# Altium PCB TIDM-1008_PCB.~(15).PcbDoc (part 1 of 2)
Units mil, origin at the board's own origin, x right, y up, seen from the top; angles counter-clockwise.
Board outline 2200 x 2300 mil, 4 copper layers (Top Layer, Power Layer, Ground Plane, Bottom Layer), stack 79.834 mil thick; 196 components, 111 nets, 520 pads, 167 vias.
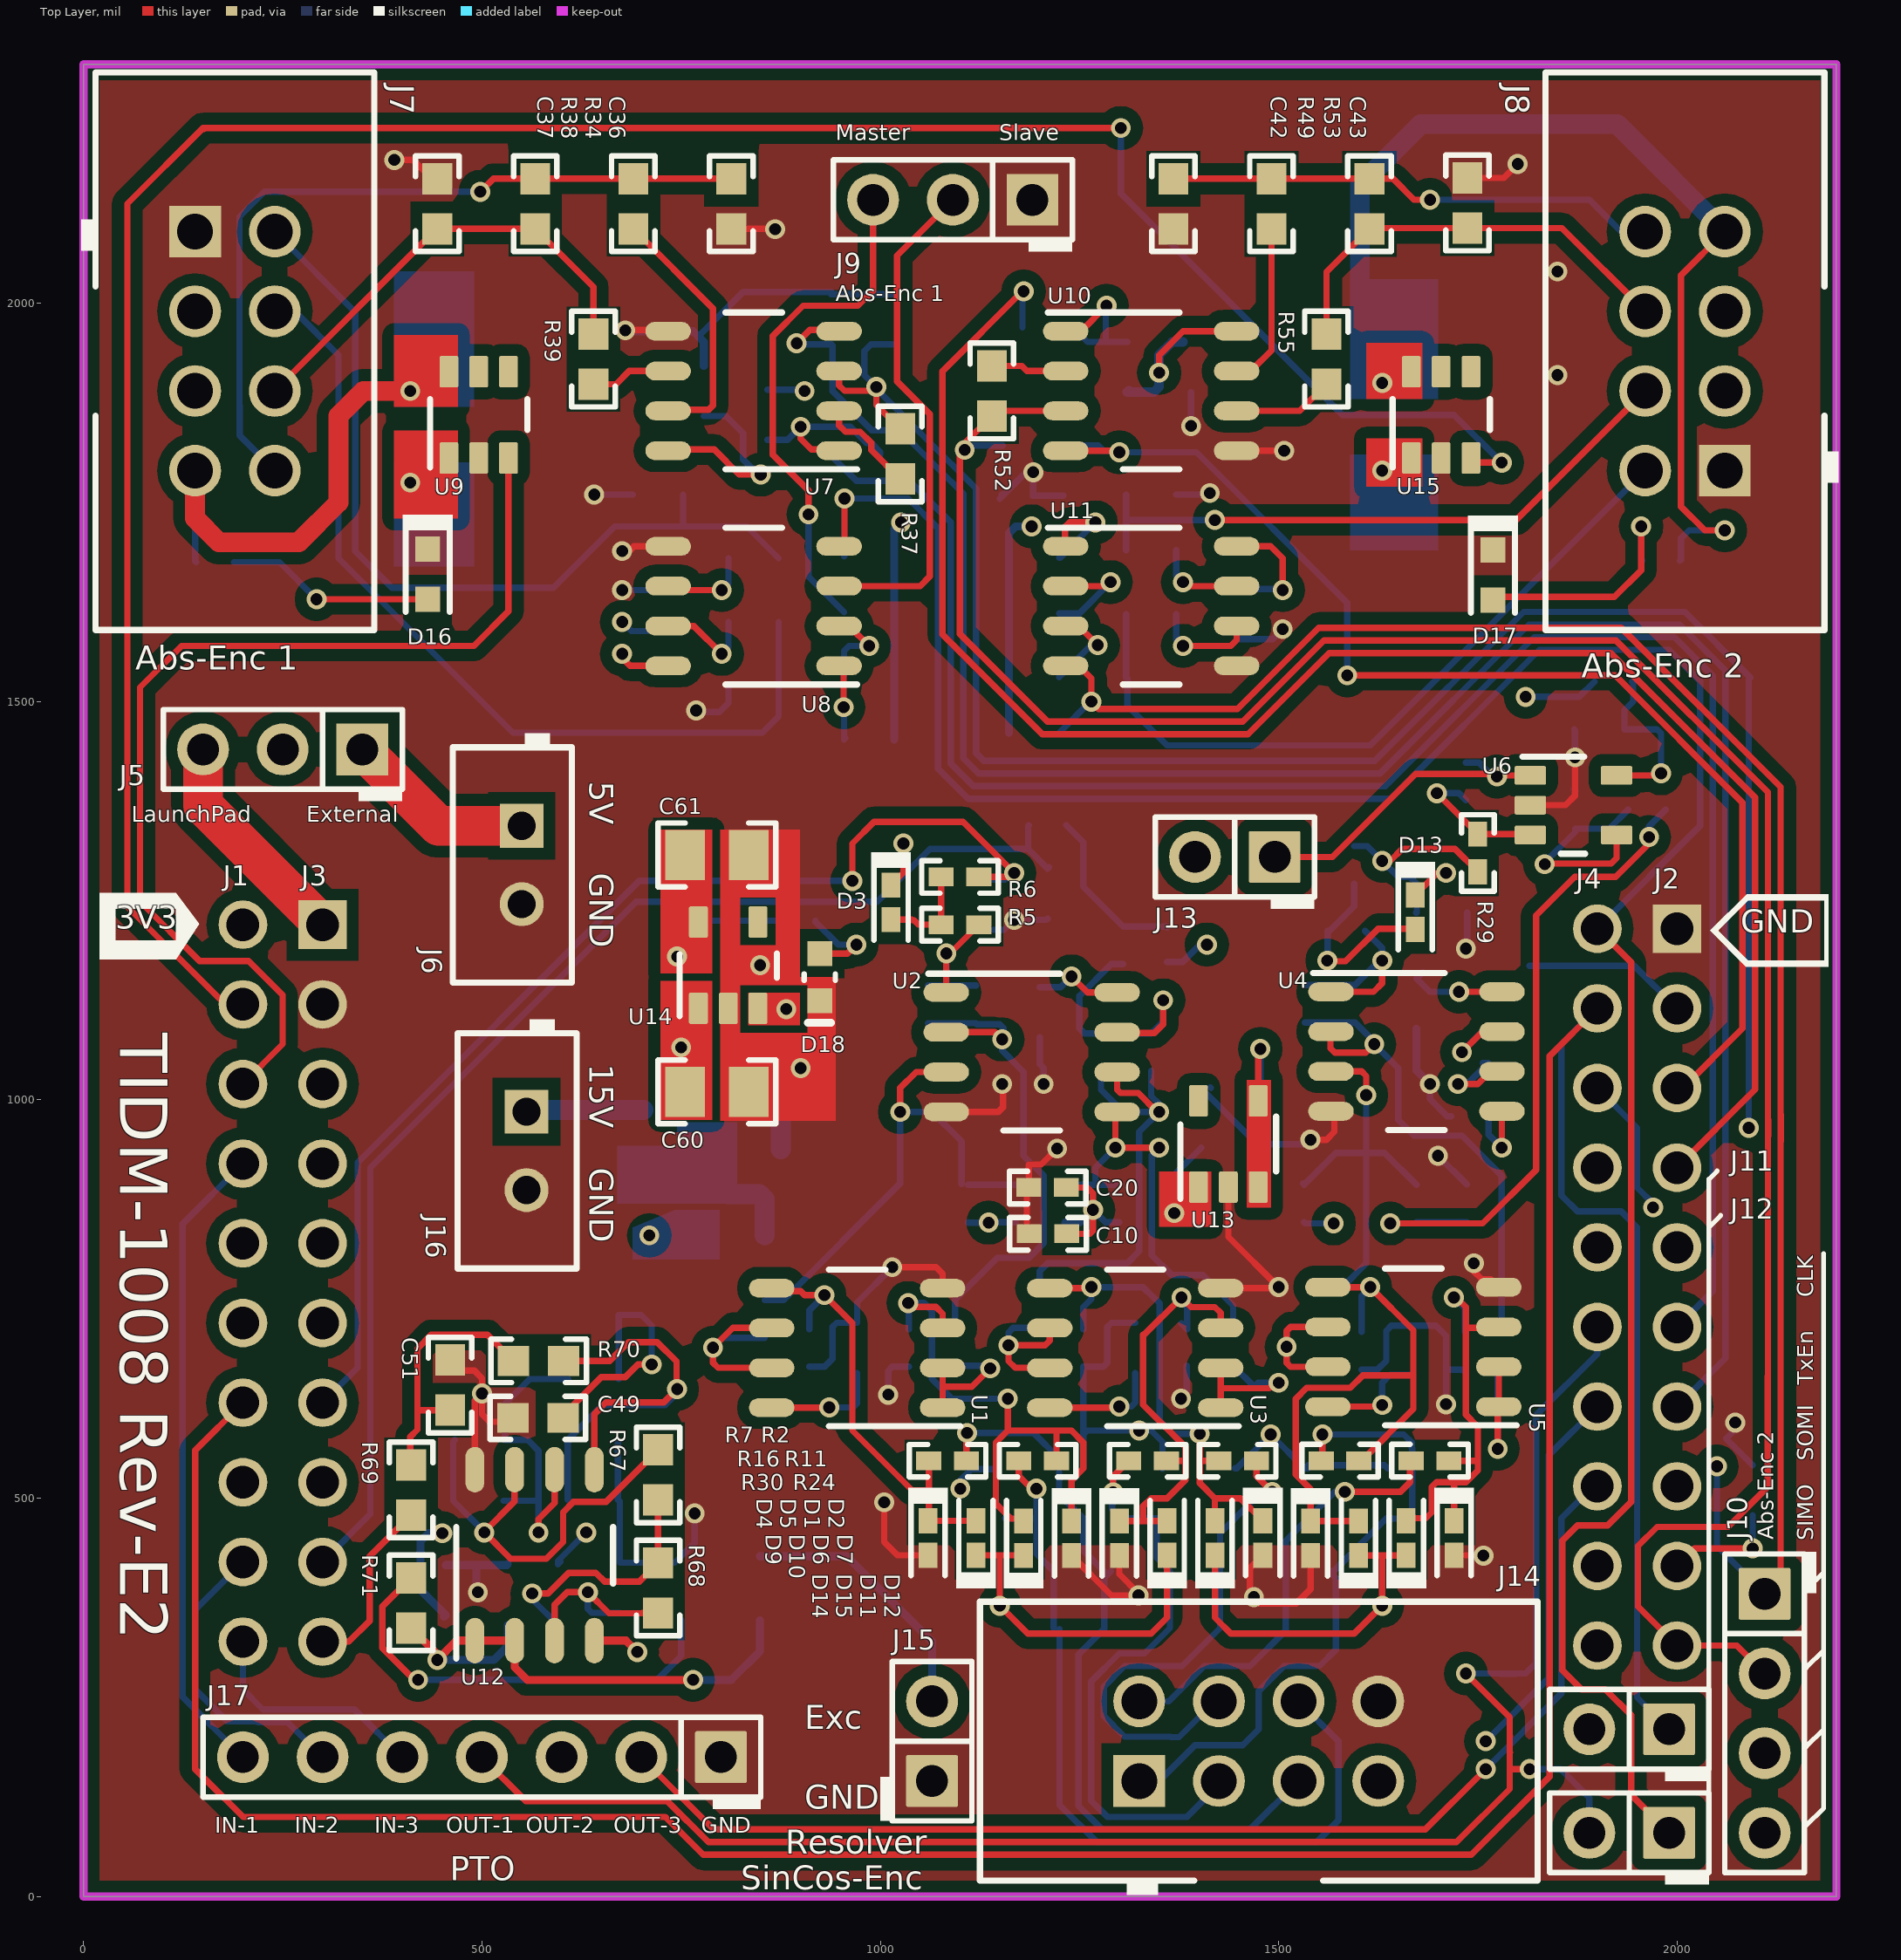
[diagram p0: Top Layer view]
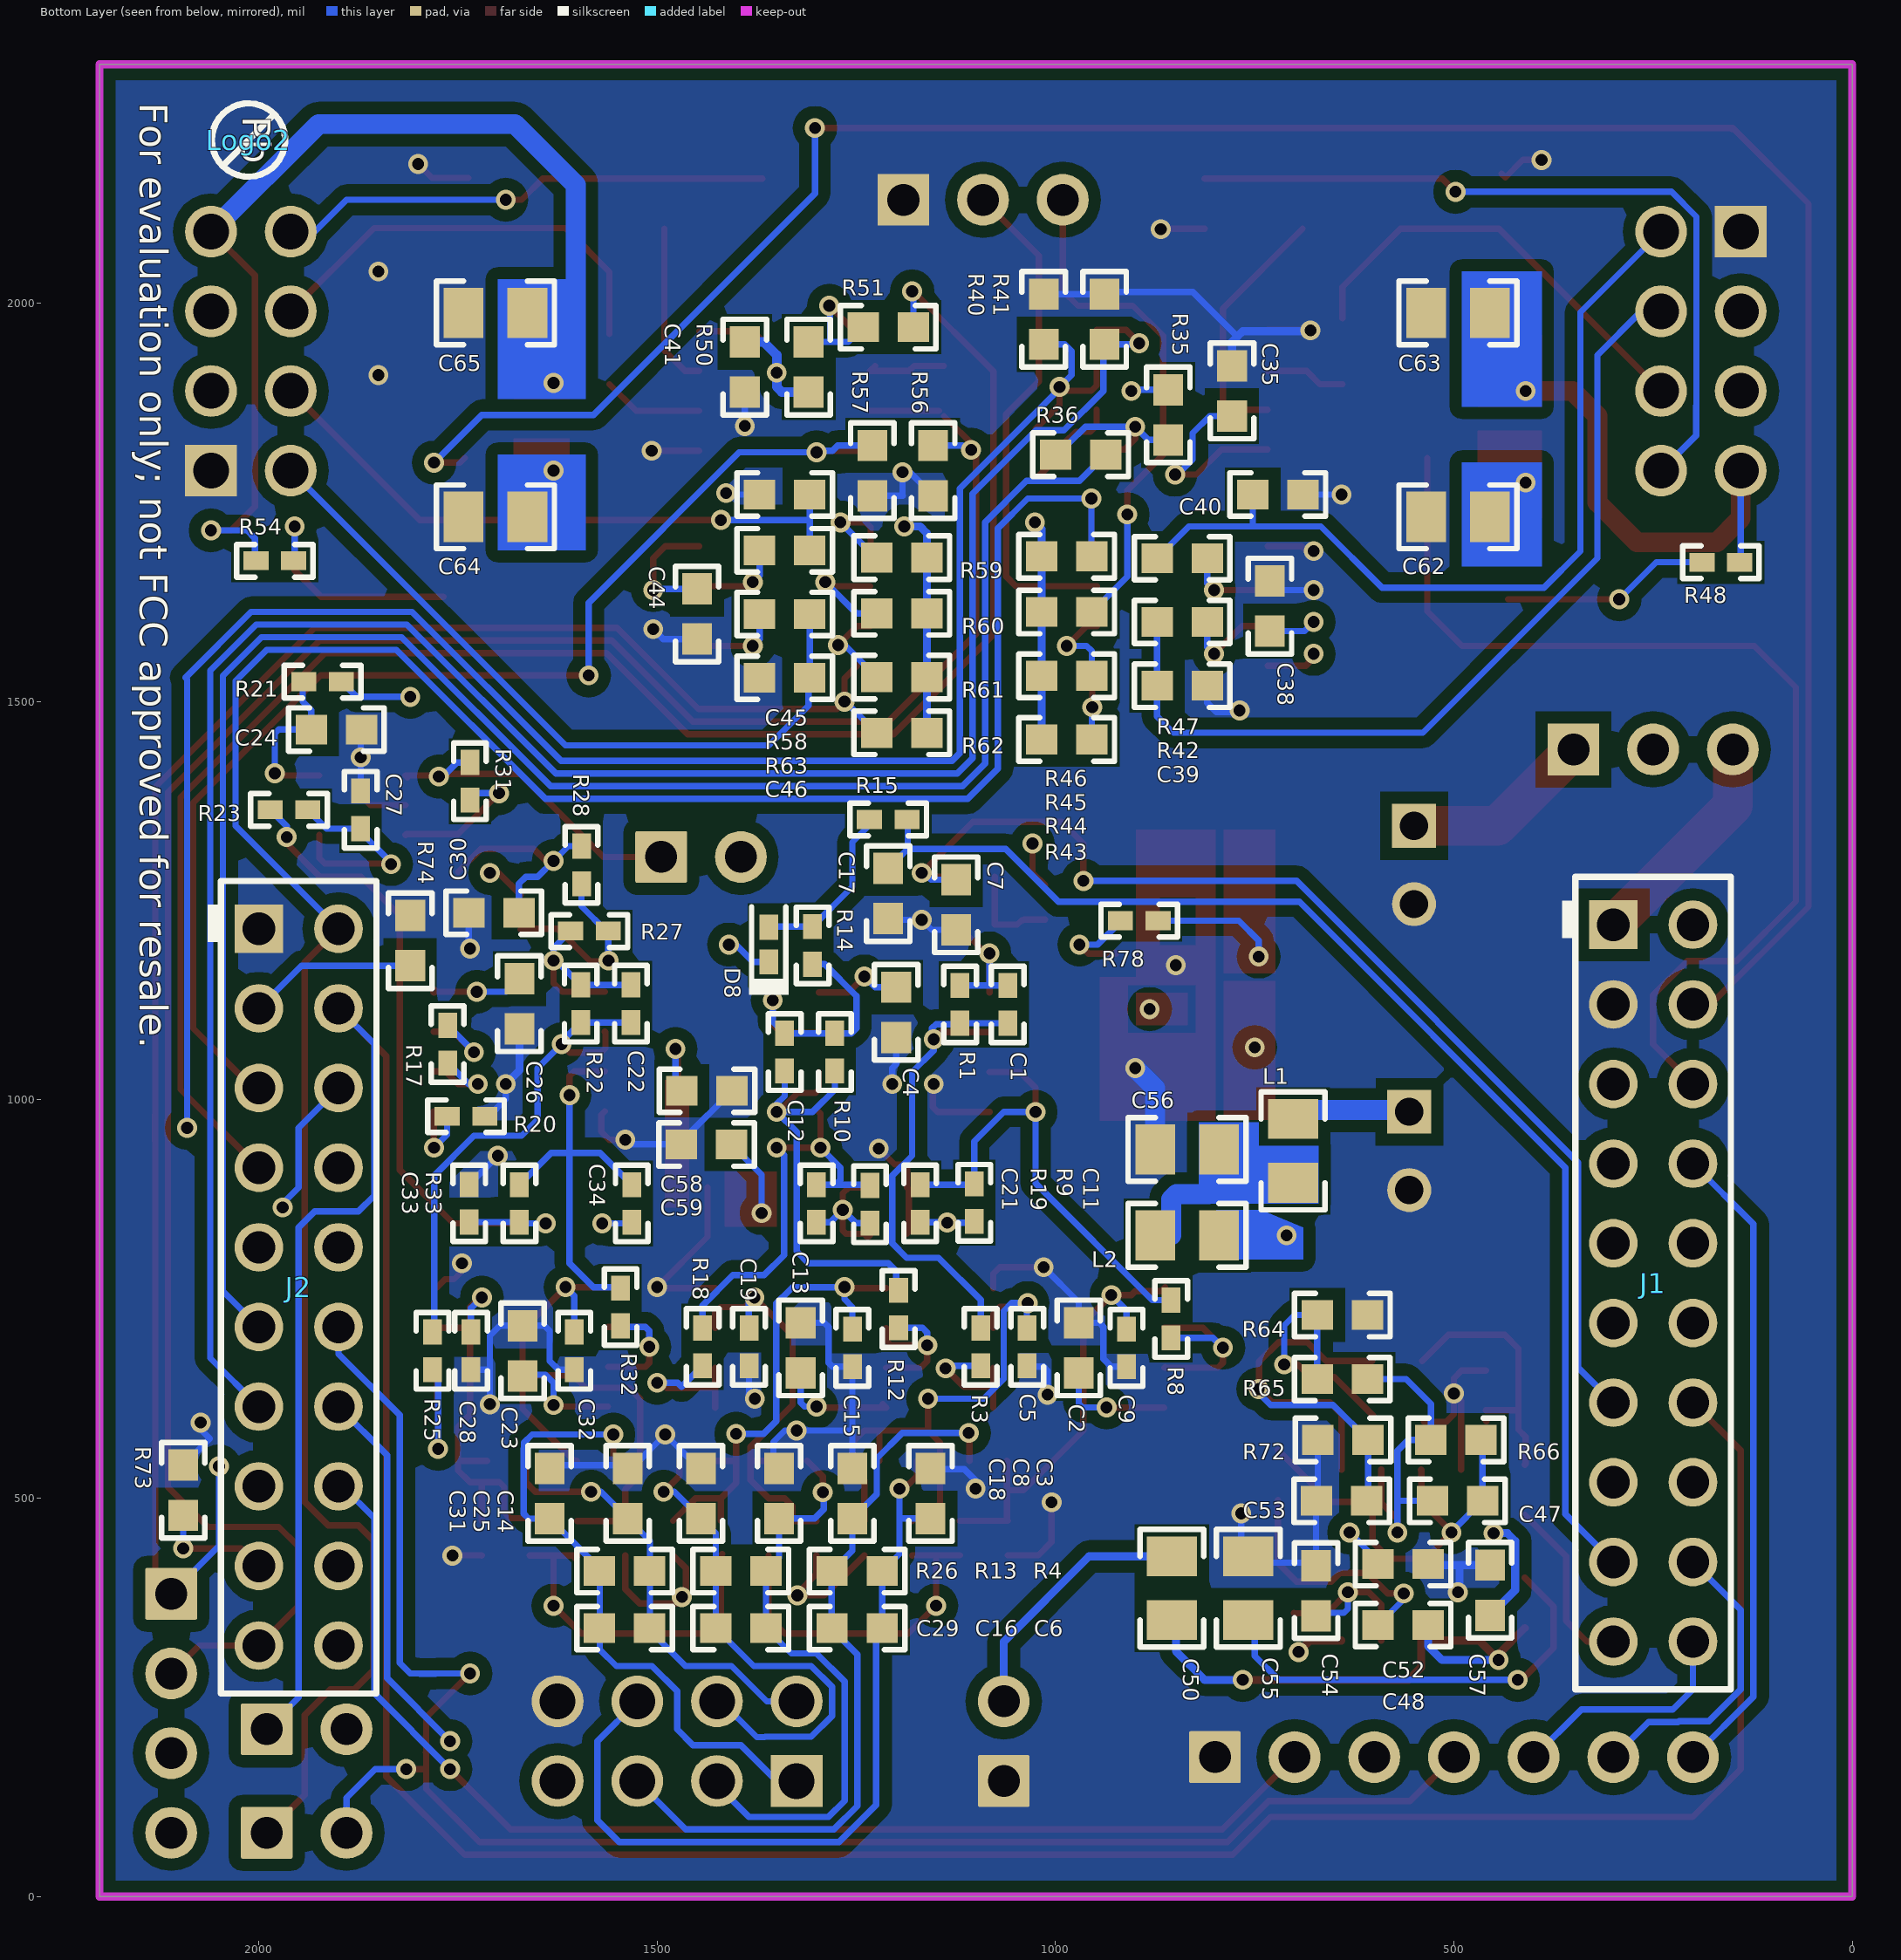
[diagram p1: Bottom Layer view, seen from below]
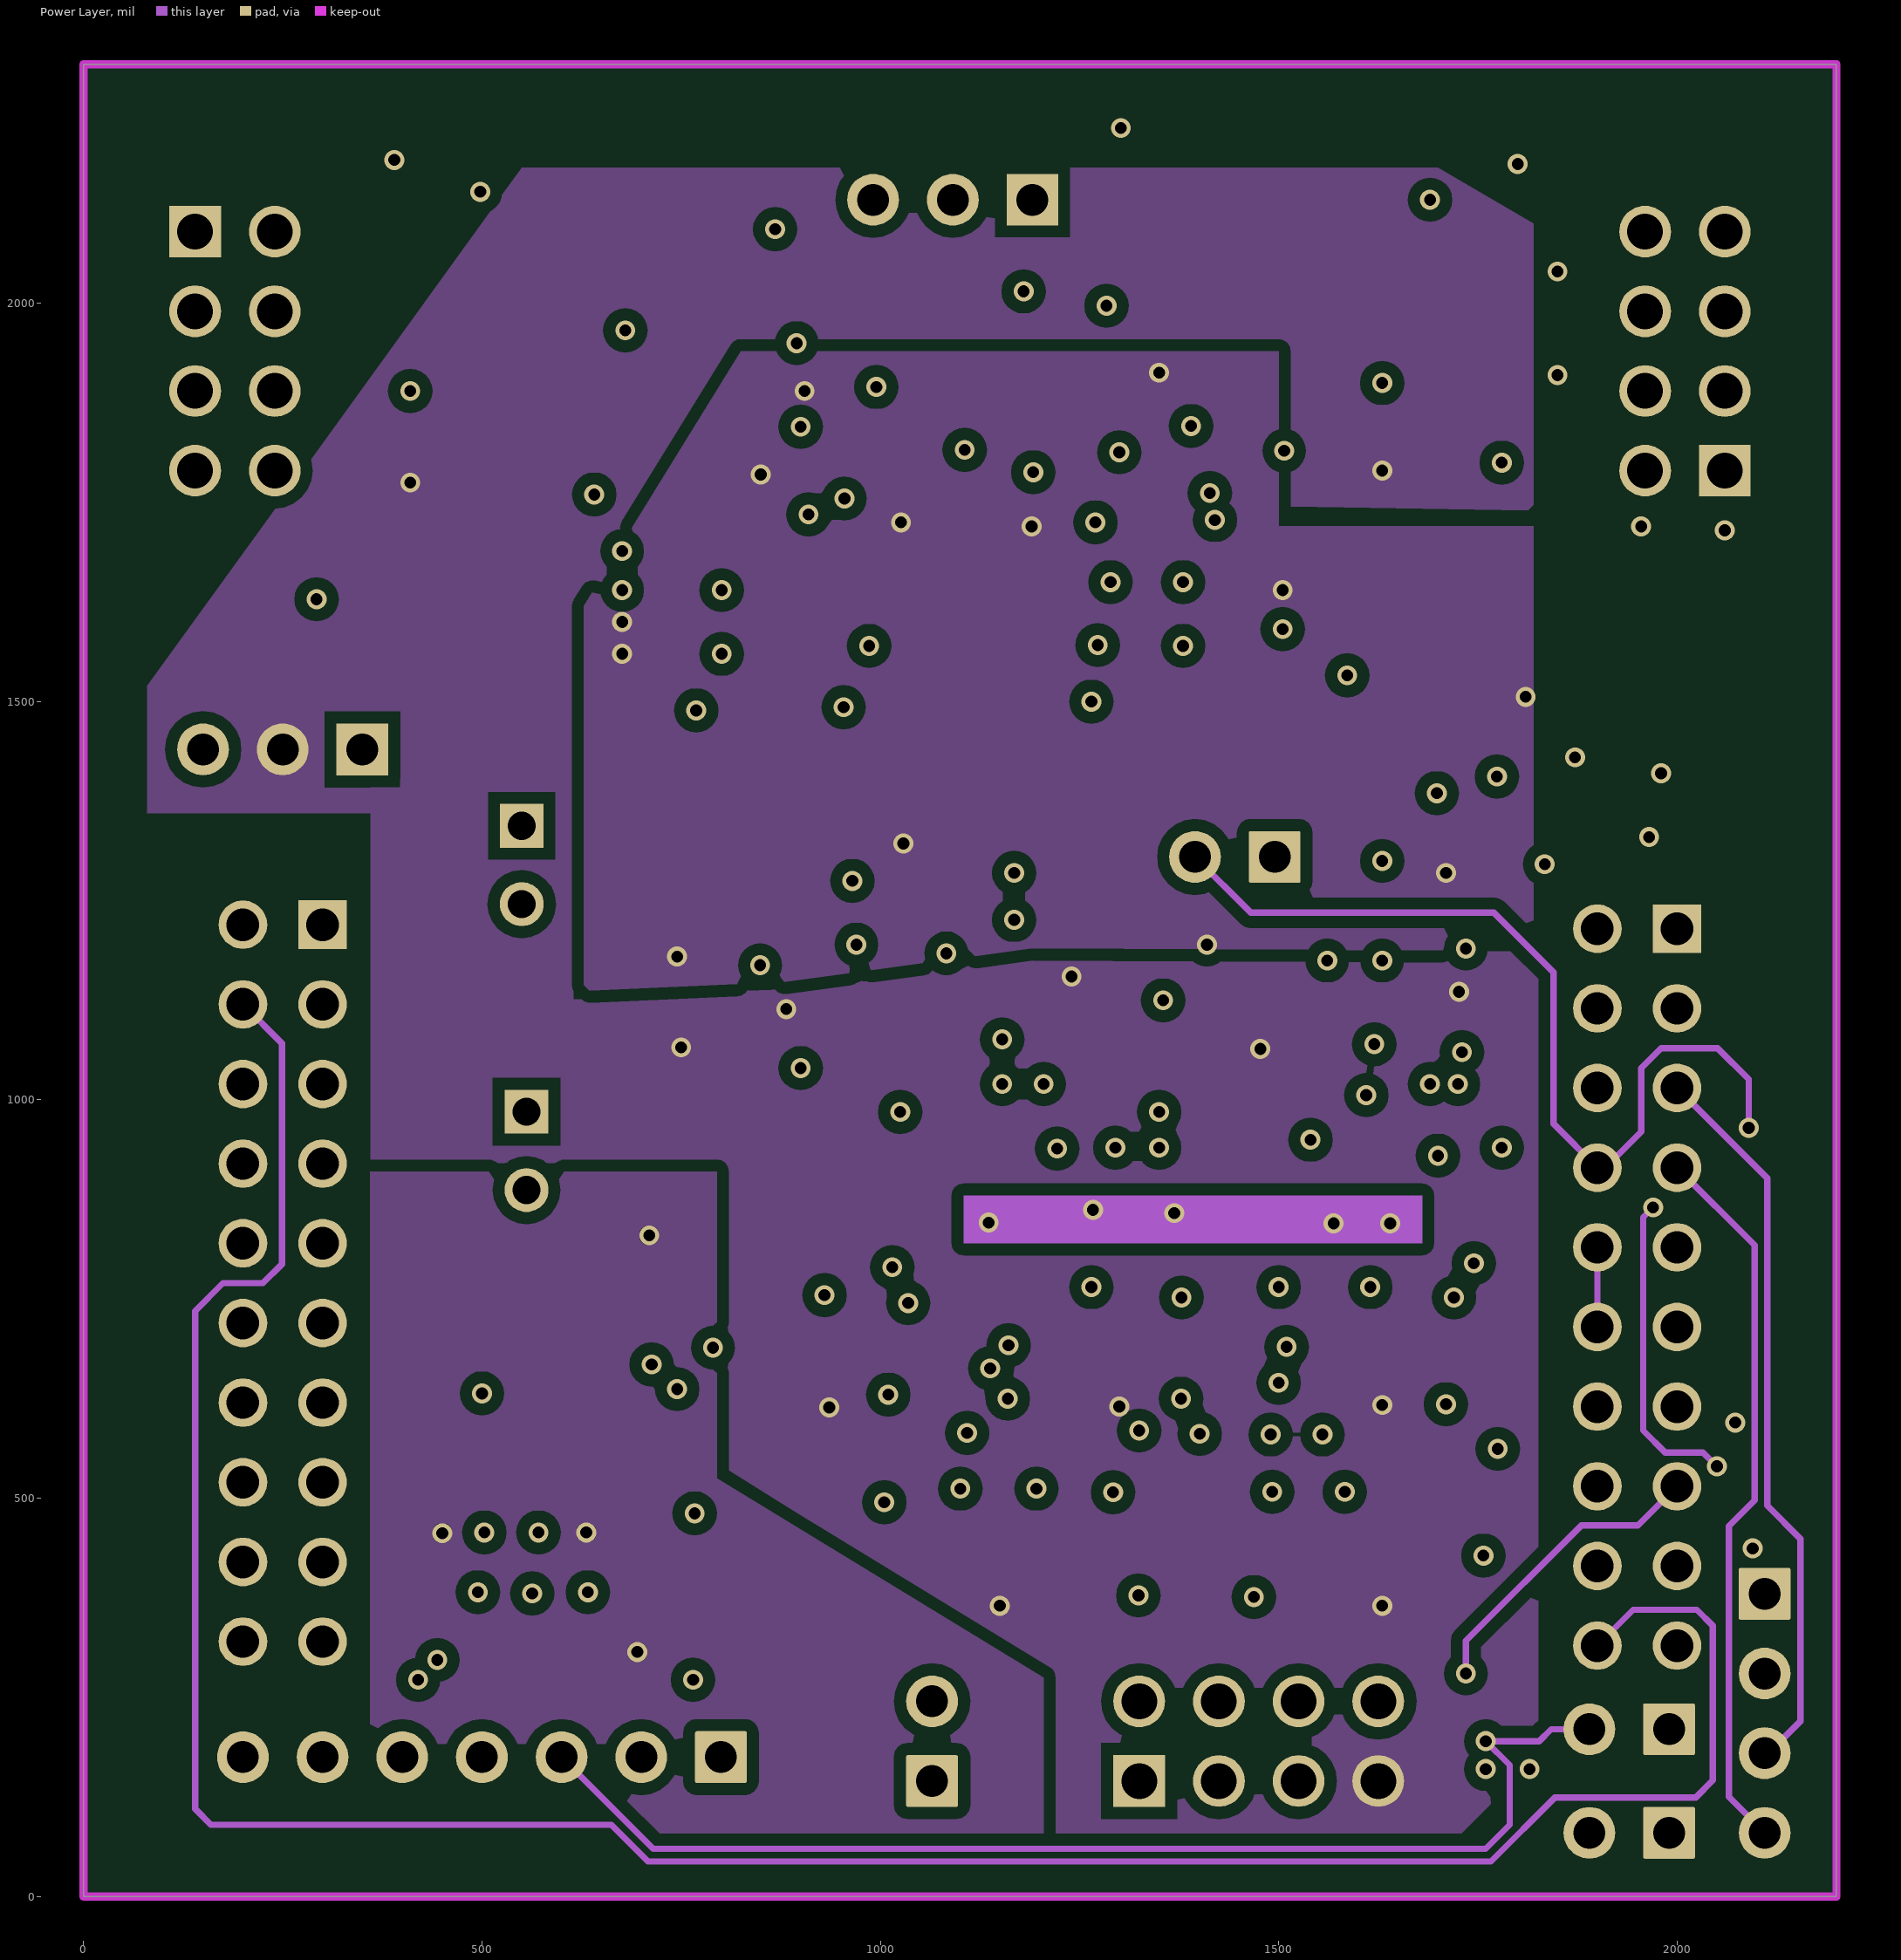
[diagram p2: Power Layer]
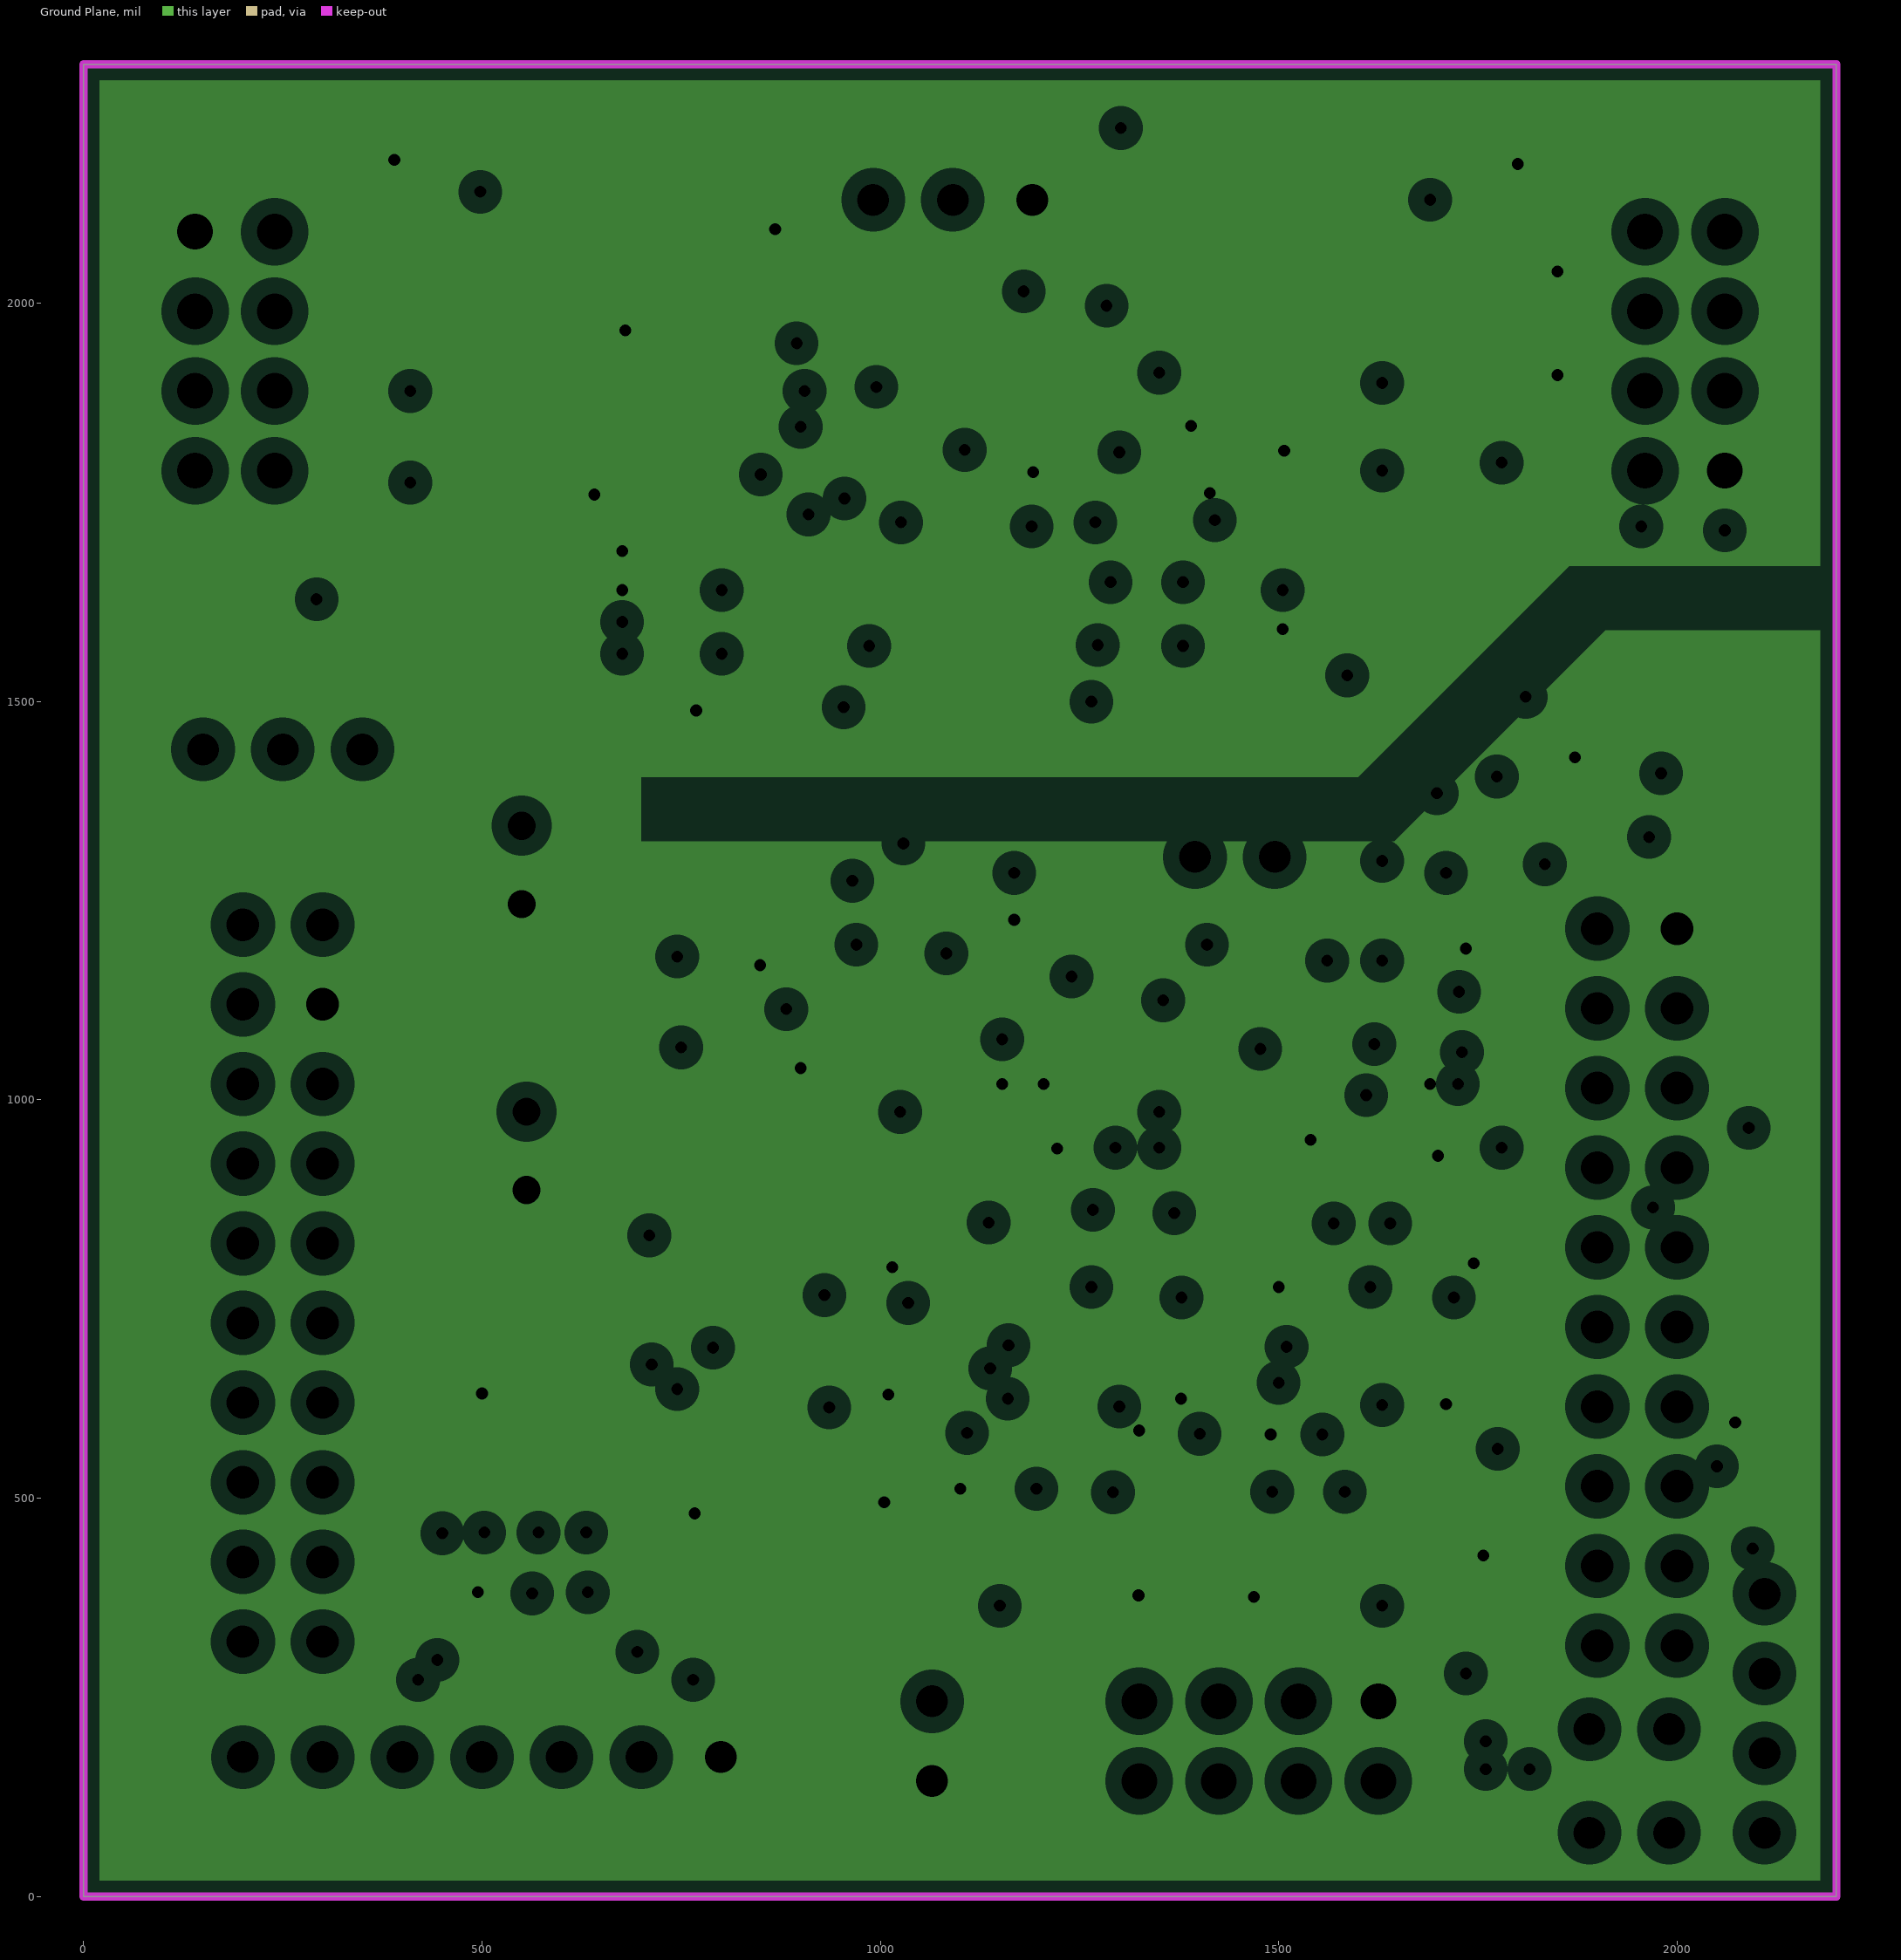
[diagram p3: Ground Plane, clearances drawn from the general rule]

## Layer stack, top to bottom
Top Solder: solder mask 0.4, Solder Resist, Dk 3.5
Top Layer: signal copper 1.4
Dielectric1: core 59.2, FR-4, Dk 4.8
Power Layer: signal copper 1.417
Dielectric 3: prepreg 5, Dk 4.2
Ground Plane: plane copper 1.417, net GND
Dielectric 2: core 10, Dk 4.2
Bottom Layer: signal copper 1.4
Bottom Solder: solder mask 0.4, Solder Resist, Dk 3.5

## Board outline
0,0 2200,0 2200,2300 0,2300

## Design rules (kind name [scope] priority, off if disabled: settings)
AcuteAngle [All] p1: minimum=4.50000000000000E+0001 checktracksonly=FALSE
AssemblyTestPointUsage [All] p1: valid=2
Clearance Clearance_Keepouts [((IsTrack Or IsArc) And Not InPoly) And IsFree and IsKeepOut vs ((IsTrack Or IsArc) And Not InPoly) And IsFree and IsKeepOut] p1: gap=0 ignorepadtopadclearanceinfootprint=FALSE
Clearance Clearance_Poly [InPolygon] p2: gap=15 ignorepadtopadclearanceinfootprint=FALSE except(0: Arc-Hole Track-Hole SMDPad-Hole THPad-Hole Via-Hole Fill-Hole Poly-Hole Region-Hole Text-Hole; 25: Arc-Text)
Clearance [All] p3: gap=7.87 ignorepadtopadclearanceinfootprint=FALSE except(0: Arc-Hole Track-Hole SMDPad-Hole THPad-Hole Via-Hole Fill-Hole Poly-Hole Region-Hole Text-Hole)
ComponentClearance ComponentClearance_1 [All] p1: gap=10 collisioncheckmode=3 verticalgap=10 showdistances=FALSE
ComponentClearance ComponentClearance_MountingHoles_FiducialMarks [InComponentClass('Mounting Holes') vs InComponentClass('FiducialMark')] p2: gap=50 collisioncheckmode=3 verticalgap=10 showdistances=FALSE
ComponentClearance ComponentClearance_Shunt [InComponentClass('Header') vs InComponentClass('Shunt')] p3: gap=0 collisioncheckmode=3 verticalgap=0 showdistances=FALSE
ComponentClearance ComponentClearance_Logo [InComponentClass('Logo')] p4: gap=50 collisioncheckmode=3 verticalgap=10 showdistances=FALSE
ComponentClearance ComponentClearance_ScrewToNut [(HasFootprint('NY PMS 440 0025 PH')) vs (HasFootprint('Keystone_1902C'))] p5: gap=5 collisioncheckmode=3 verticalgap=10 showdistances=FALSE
ComponentClearance ComponentClearance_MountingHoles [InComponentClass('Mounting Holes')] p6: gap=250 collisioncheckmode=3 verticalgap=100000 showdistances=FALSE
ComponentClearance ComponentClearance_SmallPassives [HasFootprint('0201*') or HasFootprint('0402*') or HasFootprint('0508') or HasFootprint('0603*') or HasFootprint('0612') or HasFootprint('0805*') or HasFootprint('0815*') or HasFootprint('0830*') or HasFootprint('1206*') or HasFootprint('1210*') or HasFootprint('1808*') or HasFootprint('1812*') or HasFootprint('1825*') or HasFootprint('2010*') or HasFootprint('2220*') or HasFootprint('2225*') or HasFootprint('2512*') or HasFootprint('2728*') or HasFootprint('3518*') vs HasFootprint('0201*') or HasFootprint('0402*') or HasFootprint('0508') or HasFootprint('0603*') or HasFootprint('0612') or HasFootprint('0805*') or HasFootprint('0815*') or HasFootprint('0830*') or HasFootprint('1206*') or HasFootprint('1210*') or HasFootprint('1808*') or HasFootprint('1812*') or HasFootprint('1825*') or HasFootprint('2010*') or HasFootprint('2220*') or HasFootprint('2225*') or HasFootprint('2512*') or HasFootprint('2728*') or HasFootprint('3518*')] p7: gap=14.96 collisioncheckmode=3 verticalgap=10 showdistances=FALSE
ComponentClearance ComponentClearance_THtoSMT [IsThruComponent vs IsSMTComponent] p8: gap=40 collisioncheckmode=3 verticalgap=30 showdistances=FALSE
ComponentClearance ComponentClearance_THtoTH [IsThruComponent vs IsThruComponent] p9: gap=30 collisioncheckmode=3 verticalgap=30 showdistances=FALSE
DiffPairsRouting [All] p1: maxlimit=100 minlimit=10 mostfreqgap=10 toplayer_minwidth=15 toplayer_maxwidth=15 toplayer_prefwidth=15 midlayer1_minwidth=15 midlayer1_maxwidth=15 midlayer1_prefwidth=15 bottomlayer_minwidth=15 bottomlayer_maxwidth=15 bottomlayer_prefwidth=15 maxuncoupledlength=1000
FabricationTestPointUsage TestPointUsage [All] p1: valid=2 allowmultiple=FALSE
FabricationTestpoint Testpoint [All] p1: side=3 testpointundercomponent=TRUE minsize=40 maxsize=100 preferedsize=60 minholesize=0 maxholesize=40 preferedholesize=32 testpointgrid=1 allowsidetop=TRUE allowsidebottom=TRUE usegrid=TRUE gridtolerance=0.01
FanoutControl Fanout_LCC [IsLCC] p1: bgadir=Out bgaviamode=Centered fanoutstyle=Auto fanoutdirection=Alternating viagrid=1 // Fanout_LCC (Default Rule)
FanoutControl Fanout_BGA [IsBGA] p2: bgadir=Out bgaviamode=Centered fanoutstyle=Auto fanoutdirection=Alternating viagrid=1 // Fanout_BGA (Default Rule)
FanoutControl Fanout_Default [All] p4: bgadir=Out bgaviamode=Centered fanoutstyle=Auto fanoutdirection=Alternating viagrid=1 // Fanout_Default (Default Rule)
FanoutControl Fanout_Small [(CompPinCount < 5)] p5: bgadir=Out bgaviamode=Centered fanoutstyle=Auto fanoutdirection=OutThenIn viagrid=1 // Fanout_Small (Default Rule)
HoleSize [All] p1: absolutevalues=TRUE maxlimit=251 minlimit=7.87 maxpercent=80.000 minpercent=20.000
MinimumAnnularRing MinimumAnnularRing_ThermalPadVias [IsVia and InAnyComponent] p1: minimumring=5.91
MinimumAnnularRing [All] p2: minimumring=5
MinimumSolderMaskSliver MinimumSolderMaskSliver_Logo [InComponentClass('Logo') vs InComponentClass('Logo')] p1: minsoldermaskwidth=0.7
MinimumSolderMaskSliver [All] p2: minsoldermaskwidth=3.94
PlaneClearance [All] p1: clearance=20
PlaneConnect [All] p1: planeconnectstyle=Direct reliefexpansion=10 reliefentries=4 reliefconductorwidth=10 reliefairgap=5
PolygonConnect PolygonConnect_GND [InNet('GND')] p1: connectstyle=Direct reliefconductorwidth=10 reliefentries=2 polygonreliefangle="90 Angle" airgapwidth=5
PolygonConnect PolygonConnect_2 [InNet('3V3')] p2: connectstyle=Direct reliefconductorwidth=10 reliefentries=4 polygonreliefangle="90 Angle" airgapwidth=5
PolygonConnect PolygonConnect_1 [InNet('1V65')] p3: connectstyle=Direct reliefconductorwidth=10 reliefentries=4 polygonreliefangle="90 Angle" airgapwidth=5
PolygonConnect [InNet('5V')] p4: connectstyle=Direct reliefconductorwidth=10 reliefentries=4 polygonreliefangle="90 Angle" airgapwidth=5
RoutingVias ThermalPadVias [IsVia and InAnyComponent] p1: holewidth=7.87 width=19.68 viastyle="Through Hole" minholewidth=7.87 minwidth=19.68 maxholewidth=12.99 maxwidth=23.62
RoutingVias "Signal Vias" [All] p2: holewidth=15 width=25 viastyle="Through Hole" minholewidth=15 minwidth=25 maxholewidth=15 maxwidth=25
SilkToBoardRegionClearance [Not ((IsComment or IsDesignator) And (Hide <> 'False')) and not InRegion(1000,500,4000,800)] p1:
SilkToSilkClearance SilkToSilkClearance_Pb-FreeLogo [(HasFootprint('Pb-Free_Overlay_Medium') OR HasFootprint('Pb-Free_Overlay_Small')) vs (HasFootprint('Pb-Free_Overlay_Medium') OR HasFootprint('Pb-Free_Overlay_Small'))] p1: silktosilkclearance=0
SilkToSilkClearance [All] p2: silktosilkclearance=4
SilkToSolderMaskClearance SilkToComponentPadClearance [IsPad and InAnycomponent] p1: minsilkscreentomaskgap=3 clearancetoexposedcopper=TRUE
SilkToSolderMaskClearance "Silk to Solder Mask Opening" [not isVia vs not isVia] p2: minsilkscreentomaskgap=1 clearancetoexposedcopper=FALSE
SolderMaskExpansion [All] p1: expansion=1.97
Width "PWR and GND" [All] p1: maxlimit=50 minlimit=8 preferedwidth=25 toplayer_prefwidth=10 bottomlayer_maxwidth=25 bottomlayer_prefwidth=10 minimp=50.000000 maximp=50.000000 favimp=50.000000
Width "Signal Trace" [OnLayer('Power Layer')] p2: maxlimit=25 minlimit=8 preferedwidth=12 checkconnectedcopper=TRUE
14 further rules are at their usual default settings.

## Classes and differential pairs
component class TIDM-1008_Resolver: C47 C48 C49 C50 C51 C52 C53 C54 C55 C56 C57 J15 J16 L1 L2 R64 R65 R66 R67 R68 R69 R70 R71 R72 U12
component class Header: J5 J9 J10 J11 J12 J13 J15 J17
component class TIDM-1008_SinCos: C1 C2 C3 C4 C5 C6 C7 C8 C9 C10 C11 C12 C13 C14 C15 C16 C17 C18 C19 C20 C21 C22 C23 C24 C25 C26 C27 C28 C29 C30 C31 C32 C33 C34 D1 D2 D3 D4 D5 D6 D7 D8 D9 D10 D11 D12 D13 D14 D15 J14 R1 R2 R3 R4 R5 R6 R7 R8 R9 R10 R11 R12 R13 R14 R15 R16 R17 R18 R19 R20 R21 R22 R23 R24 R25 R26 R27 R28 R29 R30 R31 R32 R33 U1 U2 U3 U4 U5 U6
component class TIDM-1008_PowerAndInterface: C58 C59 C60 C61 C62 C63 C64 C65 D18 J1 J2 J5 J6 J11 J12 J13 J17 R73 R74 R75 R76 R77 R78 U9 U13 U14 U15
component class TIDM-1008_AbsEnc: C35 C36 C37 C38 C39 C40 C41 C42 C43 C44 C45 C46 D16 D17 J7 J8 J9 J10 R34 R35 R36 R37 R38 R39 R40 R41 R42 R43 R44 R45 R46 R47 R48 R49 R50 R51 R52 R53 R54 R55 R56 R57 R58 R59 R60 R61 R62 R63 U7 U8 U10 U11
component class TIDM-1008_Hardware: Logo2 Logo4 ZZ1 ZZ2 ZZ3 ZZ4
component class AssemblyNote: ZZ1 ZZ2 ZZ3 ZZ4

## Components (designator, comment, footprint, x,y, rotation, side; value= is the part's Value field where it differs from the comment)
C1 "GRM1555C1H4R7WA01D" 0402 1060,1120 r270 bottom value=4.7pF
C2 "GRM188R71C104KA01D" 0603#1 970.97,688.73 r270 bottom value=0.1uF
C3 "GRM188R71H221KA01D" 0603#1 1157,506 r270 bottom value=220pF
C4 "GRM188R71C104KA01D" 0603#1 1200,1110 r90 bottom value=0.1uF
C5 "GRM1555C1E470JA01D" 0402 1035.68,690 r270 bottom value=47pF
C6 "GRM188R71H221KA01D" 0603#1 1249.03,337 r0 bottom value=220pF
C7 "GRM1885C2A101JA01D" 0603#1 1124.78,1244.99 r270 bottom value=100pF
C8 "GRM188R71H221KA01D" 0603#1 1255,506 r90 bottom value=220pF
C9 "GRM1555C1E470JA01D" 0402 910.97,688.73 r270 bottom value=47pF
C10 "GRM155R71C104KA88D" 0402 1210.51,831.99 r180 top value=0.1uF
C11 "GRM1555C1H4R7WA01D" 0402 1102,871 r90 bottom value=4.7pF
C12 "GRM1555C1H4R7WA01D" 0402 1340,1060 r270 bottom value=4.7pF
C13 "GRM188R71C104KA01D" 0603#1 1320,688.73 r270 bottom value=0.1uF
C14 "GRM188R71H221KA01D" 0603#1 1445,506 r270 bottom value=220pF
C15 "GRM1555C1E470JA01D" 0402 1255,688.73 r270 bottom value=47pF
C16 "GRM188R71H221KA01D" 0603#1 1395,337 r180 bottom value=220pF
C17 "GRM1885C2A101JA01D" 0603#1 1210,1259 r270 bottom value=100pF
C18 "GRM188R71H221KA01D" 0603#1 1347,506 r90 bottom value=220pF
C19 "GRM1555C1E470JA01D" 0402 1384.71,690 r270 bottom value=47pF
C20 "GRM155R71C104KA88D" 0402 1210,890 r180 top value=0.1uF
C21 "GRM1555C1H4R7WA01D" 0402 1300,870 r90 bottom value=4.7pF
C22 "GRM1555C1H4R7WA01D" 0402 1532.97,1120.76 r270 bottom value=4.7pF
C23 "GRM188R71C104KA01D" 0603#1 1669.03,685 r270 bottom value=0.1uF
C24 "GRM188R71C104KA01D" 0603#1 1902.57,1465 r0 bottom value=0.1uF
C25 "GRM188R71H221KA01D" 0603#1 1537,506 r270 bottom value=220pF
C26 "GRM188R71C104KA01D" 0603#1 1672.97,1120.76 r90 bottom value=0.1uF
C27 "GRM155R71C104KA88D" 0402 1872.18,1364.2 r90 bottom value=0.1uF
C28 "GRM1555C1E470JA01D" 0402 1733.74,685 r270 bottom value=47pF
C29 "GRM188R71H221KA01D" 0603#1 1540.97,337 r0 bottom value=220pF
C30 "GRM1885C2A101JA01D" 0603#1 1705,1235 r0 bottom value=100pF
C31 "GRM188R71H221KA01D" 0603#1 1635,506 r90 bottom value=220pF
C32 "GRM1555C1E470JA01D" 0402 1604.03,685 r270 bottom value=47pF
C33 "GRM155R71C104KA88D" 0402 1736,870.25 r90 bottom value=0.1uF
C34 "GRM1555C1H4R7WA01D" 0402 1531.88,870 r90 bottom value=4.7pF
C35 "06033D104KAT2A" 0603#1 778.5,1890 r270 bottom value=0.1uF
C36 "GRM188R71H331KA01D" 0603#2 813,2125 r90 bottom value=330pF
C37 "GRM188R71H331KA01D" 0603#1 444,2125 r90 top value=330pF
C38 "06033D104KAT2A" 0603#1 731,1620 r270 bottom value=0.1uF
C39 "GRM188R71H331KA01D" 0603#3 841,1520 r180 top value=330pF
C40 "GRM188R71H331KA01D" 0603#1 721,1760 r180 bottom value=330pF
C41 "06033D104KAT2A" 0603#1 1390,1920 r90 bottom value=0.1uF
C42 "GRM188R71H331KA01D" 0603#1 1368,2125 r90 top value=330pF
C43 "GRM188R71H331KA01D" 0603#1 1737,2126 r90 top value=330pF
C44 "06033D104KAT2A" 0603#1 1450,1610 r90 bottom value=0.1uF
C45 "GRM188R71H331KA01D" 0603#1 1340,1760 r180 bottom value=330pF
C46 "GRM188R71H331KA01D" 0603#1 1340,1530 r0 bottom value=330pF
C47 "GRM188R71H221KA01D" 0603#1 495.57,496.77 r0 bottom value=220pF
C48 "GCM188R71H472KA37D" 0603#1 563.86,340.9 r0 bottom value=4700pF
C49 "GRM1885C1E102JA01D" 0603#1 570.25,600.96 r180 top value=1000pF
C50 "TMK212BJ105KG-T" 0805_HV 854,387 r270 bottom value=1uF
C51 "GRM1885C1E102JA01D" 0603#1 460,642 r270 top value=1000pF
C52 "GRM188R71C104KA01D" 0603#1 563.86,417.27 r180 bottom value=0.1uF
C53 "GRM188R71H221KA01D" 0603#1 640.81,496.77 r0 bottom value=220pF
C54 "GRM1885C1H122JA01D" 0603#1 673,384 r270 bottom value=1200pF
C55 "GRM21BR72A473KA01L" 0805_HV 758,387 r90 bottom value=0.047uF
C56 "TMK212BJ225KG-T" 0805_HV 835,938 r180 bottom value=2.2uF
C57 "GRM188R71C104KA01D" 0603#1 454.64,384.57 r90 bottom value=0.1uF
C58 "GRM188R71C104KA01D" 0603#1 1437.49,1011.54 r0 bottom value=0.1uF
C59 "GRM188R71C104KA01D" 0603#1 1438,944 r180 bottom value=0.1uF
C60 "GRM21BR61E106KA73L" 0805_HV 795,1010 r0 top value=10uF
C61 "TMK212BJ105KG-T" 0805_HV 795,1307.59 r0 top value=1uF
C62 "GRM21BR61E106KA73L" 0805_HV 495,1732 r0 bottom value=10uF
C63 "TMK212BJ105KG-T" 0805_HV 495,1988 r0 bottom value=1uF
C64 "GRM21BR61E106KA73L" 0805_HV 1703,1732 r0 bottom value=10uF
C65 "TMK212BJ105KG-T" 0805_HV 1703,1988 r0 bottom value=1uF
D1 "1PS79SB70,115" SOD-523 1180,449.68 r90 top value=70V
D2 "1PS79SB70,115" SOD-523 1240.03,449.68 r270 top value=70V
D3 "ZHCS350TA" SOD-523 1013.49,1248 r270 top value=40V
D4 "1PS79SB70,115" SOD-523 1059.97,449.99 r270 top value=70V
D5 "1PS79SB70,115" SOD-523 1119.99,449.99 r90 top value=70V
D6 "1PS79SB70,115" SOD-523 1420.11,450 r90 top value=70V
D7 "1PS79SB70,115" SOD-523 1480.14,449.99 r270 top value=70V
D8 "ZHCS350TA" SOD-523 1360,1195 r90 bottom value=40V
D9 "1PS79SB70,115" SOD-523 1300.09,449.69 r270 top value=70V
D10 "1PS79SB70,115" SOD-523 1360.1,450 r90 top value=70V
D11 "1PS79SB70,115" SOD-523 1660.19,450 r90 top value=70V
D12 "1PS79SB70,115" SOD-523 1720.2,450.01 r270 top value=70V
D13 "ZHCS350TA" SOD-523 1671.51,1235.77 r270 top value=40V
D14 "1PS79SB70,115" SOD-523 1540.16,449.69 r270 top value=70V
D15 "1PS79SB70,115" SOD-523 1600.18,449.69 r90 top value=70V
D16 "150060GS75000" WL-SMCW_GREEN 432,1660 r270 top value=Green
D17 "150060GS75000" WL-SMCW_GREEN 1769,1659 r270 top value=Green
D18 "LG L29K-G2J1-24-Z" "LG L29K_GREEN" 924.1,1154.14 r270 top value=Green
J1 "SSW-110-21-S-D" Samtec_SSW-110-x1-x-D 250,770 r270 bottom locked
J2 "SSW-110-21-S-D" Samtec_SSW-110-x1-x-D 1950,764.98 r270 bottom locked
J5 "TSW-103-07-G-S" TSW-103-07-G-S 250,1440 r180 top locked
J6 "B2B-EH-A(LF)(SN)" JST_B2B-EH-A 550,1295 r270 top locked
J7 "70246-0801" Molex_70246-0801 190,1940 r0 top locked
J8 "70246-0801" Molex_70246-0801 2010,1940 r180 top locked
J9 "TSW-103-07-G-S" TSW-103-07-G-S 1091,2130 r180 top
J10 "TSW-104-07-G-S" TSW-104-07-G-S 2110,230 r270 top
J11 "TSW-102-07-G-S" TSW-102-07-G-S 1940,80 r180 top
J12 "TSW-102-07-G-S" TSW-102-07-G-S 1940,210 r180 top
J13 "TSW-102-07-G-S" TSW-102-07-G-S 1445,1305 r180 top
J14 "70246-0801" Molex_70246-0801 1475,195 r90 top locked
J15 "TSW-102-07-G-S" TSW-102-07-G-S 1065,195 r90 top
J16 "B2B-EH-A(LF)(SN)" JST_B2B-EH-A 556,936 r270 top locked
J17 "TSW-107-07-G-S" TSW-107-07-G-S 500,175 r180 top
L1 "LQM21FN220N00L" 0805_HV 702,936 r270 bottom value=22uH
L2 "LQM21FN220N00L" 0805_HV 835,830 r180 bottom value=22uH
Logo2 "Pb-Free Symbol" Pb-Free_Overlay_Small 2013,2205 r270 bottom
Logo4 "FCC disclaimer" FCC_disclaimer 2432,178 r90 bottom
R1 "ERA-2AEB8451X" 0402 1120,1120 r90 bottom value=8.45k
R2 "CRCW0402100RJNED" 0402 1197.5,547.01 r0 top value=100
R3 "ERJ-2RKF3301X" 0402 1093.98,690 r90 bottom value=3.30k
R4 "CRCW0603120RJNEA" 0603#1 1249.03,408.54 r180 bottom value=120
R5 "CRCW040210R0FKED" 0402 1100,1220 r180 top value=10.0
R6 "CRCW0402100RJNED" 0402 1100,1280 r0 top value=100
R7 "CRCW0402100RJNED" 0402 1084.49,547 r180 top value=100
R8 "ERJ-2RKF3301X" 0402 855,725 r90 bottom value=3.30k
R9 "ERA-2AEB8451X" 0402 1170,870 r270 bottom value=8.45k
R10 "ERA-2AEB8451X" 0402 1277.03,1060 r90 bottom value=8.45k
R11 "CRCW0402100RJNED" 0402 1448.52,547.01 r180 top value=100
R12 "ERJ-2RKF3301X" 0402 1196.99,737.46 r90 bottom value=3.30k
R13 "CRCW0603120RJNEA" 0603#1 1395,408.54 r0 bottom value=120
R14 "CRCW040210R0FKED" 0402 1305,1194 r90 bottom value=10.0
R15 "CRCW0402100RJNED" 0402 1210,1352 r180 bottom value=100
R16 "CRCW0402100RJNED" 0402 1335.51,547.01 r0 top value=100
R17 "CRCW04021K00FKED" 0402 1762.97,1070 r270 bottom value=1.00k
R18 "ERJ-2RKF3301X" 0402 1443.01,690 r90 bottom value=3.30k
R19 "ERA-2AEB8451X" 0402 1232.97,869 r270 bottom value=8.45k
R20 "CRCW04021K00FKED" 0402 1740,979.53 r0 bottom value=1.00k
R21 "CRCW04021R00JNED" 0402 1920,1525 r180 bottom value=1.0
R22 "ERA-2AEB8451X" 0402 1595.94,1120.76 r90 bottom value=8.45k
R23 "CRCW040210R0FKED" 0402 1962.18,1364.2 r180 bottom value=10.0
R24 "CRCW0402100RJNED" 0402 1690,547.02 r0 top value=100
R25 "ERJ-2RKF3301X" 0402 1782,685 r90 bottom value=3.30k
R26 "CRCW0603120RJNEA" 0603#1 1540.97,408.54 r180 bottom value=120
R27 "CRCW040210R0FKED" 0402 1585.03,1211.99 r180 bottom value=10.0
R28 "CRCW040220R0FKED" 0402 1595,1295 r90 bottom value=20.0
R29 "CRCW040226K7FKED" 0402 1750,1310 r90 top value=26.7k
R30 "CRCW0402100RJNED" 0402 1576.99,547.02 r0 top value=100
R31 "CRCW0402549KFKED" 0402 1735,1400 r90 bottom value=549k
R32 "ERJ-2RKF3301X" 0402 1546.02,740 r90 bottom value=3.30k
R33 "ERA-2AEB8451X" 0402 1672.97,870 r270 bottom value=8.45k
R34 "CRCW060310R0JNEAHP" 0603#1 690,2125 r90 top value=10
R35 "CRCW06034K70JNEA" 0603#1 858.5,1860 r90 bottom value=4.7k
R36 "CRCW060322R0JNEA" 0603#1 968.5,1810 r0 bottom value=22
R37 "CRCW06030000Z0EA" 0603#1 1025,1811 r90 top value=0
R38 "CRCW0603120RJNEA" 0603#1 567,2125 r90 top value=120
R39 "CRCW060310R0JNEAHP" 0603#1 640,1930 r90 top value=10
R40 "CRCW06034K70JNEA" 0603#1 1014.87,1980 r90 bottom value=4.7k
R41 "CRCW06034K70JNEA" 0603#1 938.5,1980 r270 bottom value=4.7k
R42 "CRCW060310R0JNEAHP" 0603#1 841,1600 r0 bottom value=10
R43 "CRCW06034K70JNEA" 0603#1 986,1452.5 r0 bottom value=4.7k
R44 "CRCW06034K70JNEA" 0603#1 986,1532.5 r0 bottom value=4.7k
R45 "CRCW06034K70JNEA" 0603#1 986,1612.5 r0 bottom value=4.7k
R46 "CRCW06034K70JNEA" 0603#1 986,1682.5 r0 bottom value=4.7k
R47 "CRCW060310R0JNEAHP" 0603#1 841,1680 r0 bottom value=10
R48 "CRCW04021K00JNED" 0402 165,1675 r180 bottom value=1.0k
R49 "CRCW060310R0JNEAHP" 0603#1 1491,2125 r90 top value=10
R50 "CRCW06034K70JNEA" 0603#1 1310,1920 r270 bottom value=4.7k
R51 "CRCW060322R0JNEA" 0603#1 1210,1970 r0 bottom value=22
R52 "CRCW06030000Z0EA" 0603#1 1140,1890 r270 top value=0
R53 "CRCW0603120RJNEA" 0603#1 1614,2125 r90 top value=120
R54 "CRCW04021K00JNED" 0402 1980,1676.84 r0 bottom value=1.0k
R55 "CRCW060310R0JNEAHP" 0603#1 1560,1930 r90 top value=10
R56 "CRCW06034K70JNEA" 0603#1 1153.63,1790 r270 bottom value=4.7k
R57 "CRCW06034K70JNEA" 0603#1 1230,1790 r90 bottom value=4.7k
R58 "CRCW060310R0JNEAHP" 0603#1 1340,1690 r180 bottom value=10
R59 "CRCW06034K70JNEA" 0603#1 1193,1680.78 r180 bottom value=4.7k
R60 "CRCW06034K70JNEA" 0603#1 1193,1610.78 r180 bottom value=4.7k
R61 "CRCW06034K70JNEA" 0603#1 1193,1530.78 r180 bottom value=4.7k
R62 "CRCW06034K70JNEA" 0603#1 1193,1460.78 r180 bottom value=4.7k
R63 "CRCW060310R0JNEAHP" 0603#1 1340,1610 r180 bottom value=10
R64 "CRCW060310K0JNEA" 0603#1 640,730 r0 bottom value=10k
R65 "CRCW06035K10JNEA" 0603#1 640.12,649.58 r180 bottom value=5.1k
R66 "CRCW060368K0JNEA" 0603#1 497.36,573.14 r180 bottom value=68k
R67 "CRCW06033K30JNEA" 0603#1 721.08,529.26 r270 top value=3.3k
R68 "CRCW06033K30JNEA" 0603#1 721.08,387.33 r270 top value=3.3k
R69 "CRCW060310K0JNEA" 0603#1 411.15,510.47 r90 top value=10k
R70 "CRCW06035K10JNEA" 0603#1 571.12,672.37 r0 top value=5.1k
R71 "RT0603DRE0747RL" 0603#1 411.09,368.54 r270 top value=47.0
R72 "CRCW060368K0JNEA" 0603#1 639.29,573.14 r180 bottom value=68k
R73 "CRCW0603150KFKEA" 0603#1 2095,510 r270 bottom value=150k
R74 "CRCW0603150KFKEA" 0603#1 1810,1200 r270 bottom value=150k
R78 "CRCW04021K00JNED" 0402 895,1225 r180 bottom value=1.0k
U1 "OPA2365AIDR" D0008A_N 970.97,688.73 r180 top
U2 "OPA2365AIDR" D0008A_N 1190,1060 r0 top
U3 "OPA2365AIDR" D0008A_N 1320,688.73 r180 top
U4 "OPA2365AIDR" D0008A_N 1672.97,1060.76 r0 top
U5 "OPA2365AIDR" D0008A_N 1669.03,690 r180 top
U6 "TLV3201AIDBVR" DBV0005A_N 1870,1370.01 r0 top
U7 "SN65HVD78D" D0008A_N 841,1890 r180 top
U8 "SN65HVD78D" D0008A_N 841,1620 r180 top
U9 "TPS22918QDBVRQ1" DBV0006A_N 496,1860 r90 top
U10 "SN65HVD78D" D0008A_N 1340,1890 r0 top
U11 "SN65HVD78D" D0008A_N 1340,1620 r0 top
U12 "OPA2209AIDR" D0008A_N 566.12,428.57 r90 top
U13 "REF2033AIDDCR" DDC0005A_N 2595.33,766.85 r180 top
U14 "TLV70233DBVR" DBV0005A_N 809.1,1169.14 r90 top
U15 "TPS22918QDBVRQ1" DBV0006A_N 1704,1860 r90 top
ZZ1 "This Assembly Note is for PCB labels only" AssemblyNoteLabel 185,3938 r0 top
ZZ2 "These assemblies are ESD sensitive, ESD precautions shall be observed." AssemblyNote 185,3829.11 r0 top
ZZ3 "These assemblies must be clean and free from flux and all contaminants. Use of no clean flux is not acceptable." AssemblyNote 185,3740.56 r0 top
ZZ4 "These assemblies must comply with workmanship standards IPC-A-610 Class 2, unless otherwise specified." AssemblyNote 185,3652 r0 top

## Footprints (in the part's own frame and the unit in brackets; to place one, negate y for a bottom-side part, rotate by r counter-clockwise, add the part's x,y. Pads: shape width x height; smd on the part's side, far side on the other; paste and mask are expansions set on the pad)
0402 [mm] "0402 from SM-752 data"
  rect 0.8x0.6 smd: 1(-0.6,0) 2(0.6,0)
  silkscreen extent -1.22,-0.52 1.22,0.52, body extent -0.55,-0.3 0.55,0.3, height 0.6
0603#1 [mm] "0603 from SM-752 data"
  rect 1x0.95 smd: 1(-0.8,0) 2(0.8,0)
  silkscreen extent -1.52,-0.69 1.52,0.69, body extent -0.87,-0.47 0.87,0.47, height 1
0603#2 [mm] "0603 from SM-752 data"
  rect 1x0.95 smd far side: 1(-0.8,0) 2(0.8,0)
  body extent -0.87,-0.47 0.87,0.47, height 1
0603#3 [mm] "0603 from SM-752 data"
  rect 1x0.95 smd far side: 1(0.8,0) 2(-0.8,0)
  body extent -0.87,-0.47 0.87,0.47, height 1
0805_HV [mil] "0805 with 30mil clearance between pads"
  rect 50x63 smd: 1(-40,0) 2(40,0)
  silkscreen extent -74,-40 74,40, body extent -43,-29 43,29, height 57
AssemblyNote [mil] "Assembly Note"
AssemblyNoteLabel [mil] "Assembly Note for PCB Labels"
D0008A_N [mm] "SOIC, 8-Leads, Body 4.9x3.9mm, Pitch 1.27mm, IPC Medium Density"
  oval 1.45x0.6 smd: 1(-2.725,1.905) 2(-2.725,0.635) 3(-2.725,-0.635) 4(-2.725,-1.905) 5(2.725,-1.905) 6(2.725,-0.635) 7(2.725,0.635) 8(2.725,1.905)
  silkscreen extent -3.3,-2.5 0.9,2.5, body extent -3,-2.45 3,2.45, height 1.63
DBV0005A_N [mm] "SOT23, 5-Leads, Body 2.9x1.6mm, Pitch 0.95mm, Lead Span 2.8mm, IPC Medium Density"
  rrect17% 1x0.6 smd: 1(-1.375,0.95) 2(-1.375,0) 3(-1.375,-0.95) 4(1.375,-0.95) 5(1.375,0.95)
  silkscreen extent -1.63,-1.55 0.38,1.55, body extent -1.42,-1.46 1.42,1.46, height 1.09
DBV0006A_N [mm] "SOT23, 6-Leads, Body 2.9x1.6mm, Pitch 0.95mm, Lead Span 2.8mm, IPC Medium Density"
  rrect17% 1x0.6 smd: 1(-1.375,0.95) 2(-1.375,0) 3(-1.375,-0.95) 4(1.375,-0.95) 5(1.375,0) 6(1.375,0.95)
  silkscreen extent -1.68,-1.55 0.5,1.55, body extent -1.42,-1.46 1.42,1.46, height 1.12
DDC0005A_N [mm]
  rrect17% 0.6x1 smd: 1(30.375,-3.142) 2(29.425,-3.142) 3(28.475,-3.142) 4(28.475,-5.892) 5(30.375,-5.892)
  silkscreen extent 27.9,-5.39 30.95,-2.77, body extent 27.98,-5.92 30.88,-3.11, height 1.1
FCC_disclaimer [mil]
JST_B2B-EH-A [mm] "Header (Shrouded), 2.5mm, 2x1, TH"
  rect 1.4x1.4 hole 0.9: 1(-1.25,0)
  round 1.4 hole 0.9: 2(1.25,0)
  silkscreen extent -4.2,-2.2 3.75,1.6, body extent -3.75,-2.2 3.75,1.6, height 6
"LG L29K_GREEN" [mm] "OSRAM"
  rect 0.8x0.8 smd paste-0.4: 1(-0.75,0) 2(0.75,0)
  silkscreen extent -0.1,-0.5 1.45,0.5, body extent -0.9,-0.45 0.9,0.45, height 0.67
Molex_70246-0801 [mm] "Header(shrouded), 2.54mm, 4x2, TH"
  rect 1.65x1.65 hole 1.14: 1(-1.27,3.81)
  round 1.65 hole 1.14: 2(1.27,3.81) 3(-1.27,1.27) 4(1.27,1.27) 5(-1.27,-1.27) 6(1.27,-1.27) 7(-1.27,-3.81) 8(1.27,-3.81)
  silkscreen extent -4.9,-8.89 4.44,8.89, body extent -4.44,-8.89 4.45,8.89, height 9.27
Pb-Free_Overlay_Small [mil]
  silkscreen extent -46,-46 46,46
Samtec_SSW-110-x1-x-D [mm] "Receptacle, 2.54mm, 10x2, TH"
  rect 1.55x1.55 hole 1.04: 1(-11.43,-1.27)
  round 1.55 hole 1.04: 2(-11.43,1.27) 3(-8.89,-1.27) 4(-8.89,1.27) 5(-6.35,-1.27) 6(-6.35,1.27) 7(-3.81,-1.27) 8(-3.81,1.27) 9(-1.27,-1.27) 10(-1.27,1.27) 11(1.27,-1.27) 12(1.27,1.27) 13(3.81,-1.27) 14(3.81,1.27) 15(6.35,-1.27) 16(6.35,1.27) 17(8.89,-1.27) 18(8.89,1.27) 19(11.43,-1.27) 20(11.43,1.27)
  silkscreen extent -12.95,-2.9 12.95,2.48, body extent -12.95,-2.48 12.95,2.48, height 8.51
SOD-523 [mm] "NXP Semiconductor recommended land pattern, nominal STEP model"
  rect 0.8x0.6 smd paste-0.05: 1(-0.55,0) 2(0.55,0)
  silkscreen extent -1.6,-0.64 1.2,0.63, body extent -0.8,-0.4 0.8,0.4, height 0.72
TSW-102-07-G-S [mm]
  rrect6% 1.65x1.65 hole 1.016: 1(-1.27,0)
  round 1.65 hole 1.016: 2(1.27,0)
  silkscreen extent -2.54,-1.27 2.54,1.65, body extent -2.54,-1.27 2.54,1.27, height 8.38
TSW-103-07-G-S [mm] "Samtec 100mil, 1x3, 230 mil above insulator"
  rect 1.65x1.65 hole 1.016: 1(-2.54,0)
  round 1.65 hole 1.016: 2(0,0) 3(2.54,0)
  silkscreen extent -3.81,-1.27 3.81,1.65, body extent -3.81,-1.27 3.81,1.27, height 8.38
TSW-104-07-G-S [mm]
  rrect6% 1.65x1.65 hole 1.016: 1(-3.81,0)
  round 1.65 hole 1.016: 2(-1.27,0) 3(1.27,0) 4(3.81,0)
  silkscreen extent -5.16,-1.27 5.08,1.65, body extent -5.08,-1.27 5.08,1.27, height 8.38
TSW-107-07-G-S [mm] "Samtec 100mil, 1x7, 230 mil above insulator"
  rrect6% 1.65x1.65 hole 1.016: 1(-7.62,0)
  round 1.65 hole 1.016: 2(-5.08,0) 3(-2.54,0) 4(0,0) 5(2.54,0) 6(5.08,0) 7(7.62,0)
  silkscreen extent -8.89,-1.27 8.89,1.65, body extent -8.89,-1.27 8.89,1.27, height 8.38
WL-SMCW_GREEN [mm] "WURTH"
  rect 0.8x0.8 smd: 1(-0.8,0) 2(0.8,0)
  silkscreen extent -1.9,-0.8 1.2,0.8, body extent -0.85,-0.45 0.85,0.45, height 0.8

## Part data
C1 C11 C12 C21 C22 C34: "CAP, CERM, 4.7 pF, 50 V, +/- 1%, C0G/NP0, 0402", Cap_Case=0402, Manufacturer=MuRata, Supplier Part Number 1=490-8210-1-ND, TempCo=C0G/NP0, Tolerance_%=1, Value1=Unknown, Value2=50V, ValueDisplayed=4.7pF
C2 C4 C13 C23 C24 C26 C52 C57 C58 C59: "CAP, CERM, 0.1 µF, 16 V, +/- 10%, X7R, 0603", Cap_Case=0603, Manufacturer=MuRata, Supplier Part Number 1=490-1532-1-ND, TempCo=X7R, Tolerance_%=10, Value1=Unknown, Value2=16V, ValueDisplayed=0.1µF
C3 C6 C8 C14 C16 C18 C25 C29 C31 C47 C53: "CAP, CERM, 220 pF, 50 V, +/- 10%, X7R, 0603", Cap_Case=0603, Manufacturer=MuRata, Supplier Part Number 1=490-1483-1-ND, TempCo=X7R, Tolerance_%=10, Value1=Unknown, Value2=50V, ValueDisplayed=220pF
C5 C9 C15 C19 C28 C32: "CAP, CERM, 47 pF, 25 V, +/- 5%, C0G/NP0, 0402", Cap_Case=0402, Manufacturer=MuRata, Supplier Part Number 1=81-GRM1555C1E470JA1D, TempCo=C0G/NP0, Tolerance_%=5, Value1=Unknown, Value2=25V, ValueDisplayed=47pF
C7 C17 C30: "CAP, CERM, 100 pF, 100 V,+/- 5%, C0G/NP0, 0603", Cap_Case=0603, Manufacturer=MuRata, Supplier Part Number 1=490-1351-1-ND, TempCo=C0G/NP0, Tolerance_%=5, Value1=Unknown, Value2=100V, ValueDisplayed=100pF
C10 C20 C27 C33: "CAP, CERM, 0.1 µF, 16 V, +/- 10%, X7R, 0402", Cap_Case=0402, Manufacturer=MuRata, Supplier Part Number 1=490-3261-1-ND, TempCo=X7R, Tolerance_%=10, Value1=Unknown, Value2=16V, ValueDisplayed=0.1µF
C35 C38 C41 C44: "CAP, CERM, 0.1uF, 25V, +/-10%, X5R, 0603", Cap_Case=0603, Manufacturer=AVX, Supplier Part Number 1=478-1244-1-ND, TempCo=X5R, Tolerance_%=10, Value1="0.048 ohm", Value2=25V, ValueDisplayed=0.1µF
C36 C37 C39 C40 C42 C43 C45 C46: "CAP, CERM, 330pF, 50V, +/-10%, X7R, 0603", Cap_Case=0603, Manufacturer=MuRata, Supplier Part Number 1=490-1486-1-ND, TempCo=X7R, Tolerance_%=10, Value1=Unknown, Value2=50V, ValueDisplayed=330pF
C48: "CAP, CERM, 4700 pF, 50 V, +/- 10%, X7R, AEC-Q200 Grade 1, 0603", Cap_Case=0603, Manufacturer=MuRata, Supplier Part Number 1=490-4932-1-ND, TempCo=X7R, Tolerance_%=10, Value1=Unknown, Value2=50V, ValueDisplayed=4700pF
C49 C51: "CAP, CERM, 1000 pF, 25 V, +/- 5%, C0G/NP0, 0603", Cap_Case=0603, Manufacturer=MuRata, Supplier Part Number 1=GRM1885C1E102JA01D-ND, TempCo=C0G/NP0, Tolerance_%=5, Value1=Unknown, Value2=25V, ValueDisplayed=1000pF
C50 C61 C63 C65: "CAP, CERM, 1 µF, 20 V, +/- 10%, X5R, 0805", Cap_Case=0805, Manufacturer="Taiyo Yuden", Supplier Part Number 1=587-1291-1-ND, TempCo=X5R, Tolerance_%=10, Value1=Unknown, Value2=20V, ValueDisplayed=1µF
C54: "CAP, CERM, 1200 pF, 50 V, +/- 5%, C0G/NP0, 0603", Cap_Case=0603, Manufacturer=MuRata, Supplier Part Number 1=490-1453-1-ND, TempCo=C0G/NP0, Tolerance_%=5, Value1=Unknown, Value2=50V, ValueDisplayed=1200pF
C55: "CAP, CERM, 0.047 µF, 100 V, +/- 10%, X7R, 0805", Cap_Case=0805, Manufacturer=MuRata, Supplier Part Number 1=490-3325-1-ND, TempCo=X7R, Tolerance_%=10, Value1=Unknown, Value2=100V, ValueDisplayed=0.047µF
C56: "CAP, CERM, 2.2 µF, 20 V, +/- 10%, X5R, 0805", Cap_Case=0805, Manufacturer="Taiyo Yuden", Supplier Part Number 1=587-1292-1-ND, TempCo=X5R, Tolerance_%=10, Value1=Unknown, Value2=20V, ValueDisplayed=2.2µF
C60 C62 C64: "CAP, CERM, 10 µF, 25 V,+/- 10%, X5R, 0805", Cap_Case=0805, Manufacturer=MuRata, Supplier Part Number 1=490-5523-1-ND, TempCo=X5R, Tolerance_%=10, Value1=Unknown, Value2=25V, ValueDisplayed=10µF
D1 D2 D4 D5 D6 D7 D9 D10 D11 D12 D14 D15: "Diode, Schottky, 70 V, 0.07 A, SOD-523", Manufacturer="NXP Semiconductor", Supplier Part Number 1=568-5975-1-ND, Value1=0.07A, Value2=0.41V
D3 D8 D13: "Diode, Schottky, 40 V, 0.35 A, SOD-523", Manufacturer="Diodes Inc.", Supplier Part Number 1=ZHCS350TACT-ND, Value1=0.35A, Value2=0.65V
D16 D17: "LED, Green, SMD", Color=Green, Manufacturer="Wurth Elektronik", Supplier Part Number 1=732-4971-1-ND, Value1=W, Value2=3.2V
D18: "LED, Green, SMD", Color=green, Manufacturer=OSRAM, Supplier Part Number 1=475-2709-1-ND, Value1=W, Value2=1.7V
J1 J2: "Receptacle, 2.54mm, 10x2, Gold, TH", Color=Black, Manufacturer=Samtec, Supplier Part Number 1=SAM1223-10-ND
J5 J9: "Header, 100mil, 3x1, Gold, TH", Color=Black, Current_A=6.3, Manufacturer=Samtec, Supplier Part Number 1=SAM1029-03-ND, Voltage_V=550
J6 J16: "Header (Shrouded), 2.5mm, 2x1, Tin, TH", Color=White, Current_A=3, Manufacturer="JST Manufacturing", Supplier Part Number 1=455-1611-ND, Voltage_V=250
J7 J8 J14: "Header(shrouded), 2.54mm, 4x2, Gold, TH", Color=Black, Current_A=2.5, Manufacturer=Molex, Supplier Part Number 1=70246-0801-ND, Voltage_V=250
J10: "Header, 100mil, 4x1, Gold, TH", Color=Black, Current_A=6.3, Manufacturer=Samtec, Supplier Part Number 1=SAM1029-04-ND, Voltage_V=550
J11 J12 J13 J15: "Header, 100mil, 2x1, Gold, TH", Color=Black, Current_A=6.3, Manufacturer=Samtec, Supplier Part Number 1=SAM1029-02-ND, Voltage_V=550
J17: "Header, 100mil, 7x1, Gold, TH", Color=Black, Current_A=6.3, Manufacturer=Samtec, Supplier Part Number 1=SAM1029-07-ND, Voltage_V=550
L1 L2: "Inductor, Shielded, Ferrite, 22 µH, 0.013 A, 0.455 ohm, SMD", Manufacturer=MuRata, Supplier Part Number 1=490-4030-1-ND, Value1="0.455 ohm", Value2=0.013A, ValueDisplayed=22µH
Logo2: library part Pb-Free
Logo4: library part FCC_disclaimer, "FCC_disclaimer"
R1 R9 R10 R19 R22 R33: "RES, 8.45 k, 0.1%, 0.063 W, 0402", Manufacturer=Panasonic, Power_W=0.063, Supplier Part Number 1=P8.45KDCCT-ND, TempCo="25 ppm/C", Tolerance_%=0.1, Value1=0.1%, Value2=0.063W, Value_Code=8k45, ValueDisplayed=8.45k
R2 R6 R7 R11 R15 R16 R24 R30: "RES, 100, 5%, 0.063 W, 0402", Manufacturer=Vishay-Dale, Power_W=0.063, Supplier Part Number 1=541-100JCT-ND, TempCo="200 ppm/C", Tolerance_%=5, Value1=5%, Value2=0.063W, Value_Code=100R, ValueDisplayed=100
R3 R8 R12 R18 R25 R32: "RES, 3.30 k, 1%, 0.1 W, AEC-Q200 Grade 0, 0402", Manufacturer=Panasonic, Power_W=0.1, Supplier Part Number 1=P3.30KLCT-ND, TempCo="100 ppm/C", Tolerance_%=1, Value1=1%, Value2=0.1W, Value_Code=3k30, ValueDisplayed=3.30k
R4 R13 R26 R38 R53: "RES, 120, 5%, 0.1 W, 0603", Manufacturer=Vishay-Dale, Power_W=0.1, Supplier Part Number 1=541-120GCT-ND, TempCo="200 ppm/C", Tolerance_%=5, Value1=5%, Value2=0.1W, Value_Code=120R, ValueDisplayed=120
R5 R14 R23 R27: "RES, 10.0, 1%, 0.063 W, 0402", Manufacturer=Vishay-Dale, Power_W=0.063, Supplier Part Number 1=541-10.0LCT-ND, TempCo="100 ppm/C", Tolerance_%=1, Value1=1%, Value2=0.063W, Value_Code=10R0, ValueDisplayed=10.0
R17 R20: "RES, 1.00 k, 1%, 0.063 W, 0402", Manufacturer=Vishay-Dale, Power_W=0.063, Supplier Part Number 1=541-1.00KLCT-ND, TempCo="100 ppm/C", Tolerance_%=1, Value1=1%, Value2=0.063W, Value_Code=1k00, ValueDisplayed=1.00k
R21: "RES, 1.0, 5%, 0.063 W, 0402", Manufacturer=Vishay-Dale, Power_W=0.063, Supplier Part Number 1=541-1.0JCT-ND, TempCo="200 ppm/C", Tolerance_%=5, Value1=5%, Value2=0.063W, Value_Code=1R00, ValueDisplayed=1.0
R28: "RES, 20.0, 1%, 0.063 W, 0402", Manufacturer=Vishay-Dale, Power_W=0.063, Supplier Part Number 1=541-20.0LCT-ND, TempCo="100 ppm/C", Tolerance_%=1, Value1=1%, Value2=0.063W, Value_Code=20R0, ValueDisplayed=20.0
R29: "RES, 26.7 k, 1%, 0.063 W, 0402", Manufacturer=Vishay-Dale, Power_W=0.063, Supplier Part Number 1=541-26.7KLCT-ND, TempCo="100 ppm/C", Tolerance_%=1, Value1=1%, Value2=0.063W, Value_Code=26k7, ValueDisplayed=26.7k
R31: "RES, 549 k, 1%, 0.063 W, 0402", Manufacturer=Vishay-Dale, Power_W=0.063, Supplier Part Number 1=541-549KLCT-ND, TempCo="100 ppm/C", Tolerance_%=1, Value1=1%, Value2=0.063W, Value_Code=549k
R34 R39 R42 R47 R49 R55 R58 R63: "RES, 10 ohm, 5%, 0.25W, 0603", Manufacturer=Vishay-Dale, Power_W=0.25, Supplier Part Number 1=541-10SACT-ND, TempCo="200 ppm/C", Tolerance_%=5, Value1=5%, Value2=0.25W, Value_Code=10R0
R35 R40 R41 R43 R44 R45 R46 R50 R56 R57 R59 R60 R61 R62: "RES, 4.7k ohm, 5%, 0.1W, 0603", Manufacturer=Vishay-Dale, Power_W=0.1, Supplier Part Number 1=71-CRCW0603J-4.7K-E3, TempCo="200 ppm/C", Tolerance_%=5, Value1=5%, Value2=0.1W, Value_Code=4k70
R36 R51: "RES, 22 ohm, 5%, 0.1W, 0603", Manufacturer=Vishay-Dale, Power_W=0.1, Supplier Part Number 1=541-22GCT-ND, TempCo="200 ppm/C", Tolerance_%=5, Value1=5%, Value2=0.1W, Value_Code=22R0
R37 R52: "RES, 0, 5%, 0.1 W, 0603", Manufacturer=Vishay-Dale, Power_W=0.1, Supplier Part Number 1=541-0.0GCT-ND, TempCo="200 ppm/C", Tolerance_%=5, Value1=5%, Value2=0.1W, Value_Code=0000, ValueDisplayed=0
R48 R54 R78: "RES, 1.0 k, 5%, 0.063 W, 0402", Manufacturer=Vishay-Dale, Power_W=0.063, Supplier Part Number 1=541-1.0KJCT-ND, TempCo="200 ppm/C", Tolerance_%=5, Value1=5%, Value2=0.063W, Value_Code=1k00, ValueDisplayed=1.0k
R64 R69: "RES, 10 k, 5%, 0.1 W, 0603", Manufacturer=Vishay-Dale, Power_W=0.1, Supplier Part Number 1=541-10KGCT-ND, TempCo="200 ppm/C", Tolerance_%=5, Value1=5%, Value2=0.1W, Value_Code=10k0, ValueDisplayed=10k
R65 R70: "RES, 5.1 k, 5%, 0.1 W, 0603", Manufacturer=Vishay-Dale, Power_W=0.1, Supplier Part Number 1=541-5.1KGCT-ND, TempCo="200 ppm/C", Tolerance_%=5, Value1=5%, Value2=0.1W, Value_Code=5k10, ValueDisplayed=5.1k
R66 R72: "RES, 68 k, 5%, 0.1 W, 0603", Manufacturer=Vishay-Dale, Power_W=0.1, Supplier Part Number 1=541-68KGCT-ND, TempCo="200 ppm/C", Tolerance_%=5, Value1=5%, Value2=0.1W, Value_Code=68k0, ValueDisplayed=68k
R67 R68: "RES, 3.3 k, 5%, 0.1 W, 0603", Manufacturer=Vishay-Dale, Power_W=0.1, Supplier Part Number 1=541-3.3KGCT-ND, TempCo="200 ppm/C", Tolerance_%=5, Value1=5%, Value2=0.1W, Value_Code=3k30, ValueDisplayed=3.3k
R71: "RES, 47.0, 0.5%, 0.1 W, 0603", Manufacturer="Yageo America", Power_W=0.1, TempCo="50 ppm/C", Tolerance_%=0.5, Value1=0.5%, Value2=0.1W, Value_Code=47R0, ValueDisplayed=47.0
R73 R74: "RES, 150 k, 1%, 0.1 W, 0603", Manufacturer=Vishay-Dale, Power_W=0.1, Supplier Part Number 1=541-150KHCT-ND, TempCo="100 ppm/C", Tolerance_%=1, Value1=1%, Value2=0.1W, Value_Code=150k
U1 U2 U3 U4 U5: "50 MHz, Low-Noise Single-Supply Rail-to-Rail Operational Amplifier, 2.2 to 5.5 V, -40 to 125 degC, 8-pin SOIC (D0008A), Green (RoHS & no Sb/Br)", Alternate Manufacturer=None, Alternate PartNumber=Equivalent, Manufacturer="Texas Instruments", Supplier Part Number 1=296-31704-2-ND, Total Supply Voltage(Max)(+5V is 5, +/-5V is 10)=5.5, Total Supply Voltage(Min)(+5V is 5, +/-5V is 10)=2.2
U6: "40-ns, microPOWER, Push-Pull Output Comparators, DBV0005A", Alternate Manufacturer="Texas Instruments", Alternate PartNumber=TLV3201AIDBVT
U7 U8 U10 U11: "3.3V-Supply RS-485 with IEC ESD Protection, D0008A", Alternate Manufacturer=None, Manufacturer="Texas Instruments"
U9 U15: "5.5-V, 2-A, 54mohm On-Resistance Load Switch, DBV0006A (SOT-23-6)", Alternate Manufacturer="Texas Instruments"
U12: "2.2 nV/rtHz, 18 MHz, Precision, RRO, Operational Amplifier, 4.5 to 36 V, -40 to 125 degC, 8-pin SOIC (D0008A), Green (RoHS & no Sb/Br)", Alternate Manufacturer="Texas Instruments", Alternate PartNumber=Equivalent, Rating=Catalog, Supplier Part Number 1=296-27783-2-ND, Total Supply Voltage(Max)(+5V is 5, +/-5V is 10)=36, Total Supply Voltage(Min)(+5V is 5, +/-5V is 10)=4.5
U13: "Low-Drift, Low-Power, Dual-Output, VREF and VREF / 2 Voltage References, DDC0005A", Alternate Manufacturer="Texas Instruments", Alternate PartNumber=REF2033AIDDCT
U14: "Single Output LDO, 300 mA, Fixed 3.3 V Output, 2 to 5.5 V Input, with Low IQ, 5-pin SOT-23 (DBV), -40 to 125 degC, Green (RoHS & no Sb/Br)", Alternate Manufacturer="Texas Instruments", Alternate PartNumber=Equivalent, Supplier Part Number 1=296-32415-2-ND
ZZ1: library part AssemblyNoteLabel, Alternate Manufacturer=-
ZZ2 ZZ3 ZZ4: library part AssemblyNote, Alternate Manufacturer=-

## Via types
v1: diameter 25, hole 15, Top Layer to Bottom Layer, 167 vias

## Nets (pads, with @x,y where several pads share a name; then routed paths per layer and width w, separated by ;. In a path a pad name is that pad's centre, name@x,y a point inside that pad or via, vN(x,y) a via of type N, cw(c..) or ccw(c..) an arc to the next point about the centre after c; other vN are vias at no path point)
1V65: C10.1 C11.1 C20.1 C21.1 C33.1 C34.1 C59.2 R9.2 R19.2 R23.1 R33.2 U13.1 | length 1262.2
  Top Layer w8: C20.1@1233.62,890 1259.74,890 1267,882.74 v1(1267,862) 1267,836 1262.99,831.99 C10.1@1234.13,831.99 ; v1(1640,845) 1756,845 1823,912 1823,1231.58 1871.55,1280.13 1923.13,1280.13 1965,1322 v1(1965,1330)
  Top Layer w12: C10.1@1234.13,831.99 C10.1@1236.12,830
  Bottom Layer w8: C11.1@1110,846.38 1110.38,846 1141,846 1141.38,846.38 R9.2@1170,846.38 ; R19.2@1232.97,845.38 1250.38,845.38 v1(1267,862) 1282.62,846.38 C21.1@1300,846.38 ; v1(1369,858) 1369,906.11 C59.2@1402.89,940 ; C34.1@1531.88,846.38 1533.26,845 v1(1569,845) ; v1(1640,845) R33.2@1676.88,845 ; R33.2@1673.35,846 R33.2@1672.97,846.38 1673.22,846.63 C33.1@1736,846.63 ; v1@1961.31,1328.69 1962.61,1330 v1(1965,1330) 1965,1343.4 R23.1@1985.8,1364.2
  Bottom Layer w12: R19.2@1232.97,845.38 R19.2@1234.35,844
  other v1: 1136,846
3V3: C35.2 C38.2 C41.2 C44.2 C61.1 D3.1 D8.1 D13.1 R21.2 R35.2 R43.2 R44.2 R45.2 R46.2 R50.2 R59.2 R60.2 R61.2 R62.2 R78.2 U7.8 U8.8 U10.8 U11.8 U14.5 | length 1823.4
  Top Layer w8: v1(676,1560) 676,1555 686,1545 U8.8@733.72,1545 ; U7.8@733.79,1816.5 791.5,1816.5 823,1785 v1(850,1785) ; D3.1@1013.49,1269.65 1029,1285.16 v1(1029,1322) ; v1@1358,1913 v1(1350,1913) 1350,1935 1380,1965 U10.8@1447.28,1965 ; U11.8@1447.28,1695 1490,1695 1505,1680 v1(1505,1640) ; D13.1@1671.51,1257.42 1699.09,1285 v1(1710,1285)
  Bottom Layer w8: v1(676,1600) 687.5,1588.5 C38.2@731,1588.5 ; v1(745,1180) 745,1200 770,1225 R78.2@871.38,1225 ; C35.2@778.5,1858.5 806.5,1858.5 827.93,1837.07 827.93,1803.9 846.83,1785 v1(850,1785) ; R35.2@858.5,1891.5 903.5,1891.5 v1(905,1890) ; D8.1@1360,1173.35 1379.85,1173.35 1395,1188.5 1401.5,1195 v1(1410,1195) ; C44.2@1450,1641.5 1503.5,1641.5 v1(1505,1640) ; v1(1810,1506) 1877.38,1506 R21.2@1896.38,1525
  Bottom Layer w10: R43.2@1017.5,1452.5 R44.2@1017.5,1532.5 R45.2@1017.5,1612.5 R46.2@1017.5,1682.5 1017.5,1716.5 v1(1026,1725) ; R62.2@1161.5,1460.78 R61.2@1161.5,1530.78 R60.2@1161.5,1610.78 R59.2@1161.5,1680.78 1161.5,1711.5 1170,1720 v1(1190,1720)
  Bottom Layer w12: R50.2@1312,1890.5 R50.2@1310,1888.5 1343.5,1888.5 1350,1895 v1(1350,1913) 1350,1935 1366.5,1951.5 C41.2@1380,1951.5
5V: C2.2 C4.2 C13.2 C23.2 C26.2 C58.2 C60.1 C62.1 C64.1 D1.1 D5.1 D6.1 D10.1 D11.1 D15.1 J5.2 J14.7 U1.8 U2.8 U3.8 U4.8 U5.8 U9.1 U13.3 U13.4 U14.1 U14.3 U15.1 | length 1810.2
  Top Layer w8: v1(410,1775) 427.73,1775 U9.1@458.6,1805.87 ; U14.3@846.5,1115 881,1115 v1(882,1114) ; U1.8@863.69,613.73 935.73,613.73 v1(936,614) ; D5.1@1119.99,428.34 1150,428.34 ; D1.1@1180,428.03 1179.69,428.34 1150,428.34 ; U3.8@1216.99,618 U3.8@1212.72,613.73 1298.73,613.73 v1(1300,615) ; v1(1240,1155) 1260,1135 U2.8@1297.29,1135 ; D10.1@1360.1,428.35 1360.1,350.1 1340,330 1185,330 v1(1150,365) 1150,428.34 ; D6.1@1418.46,430 D6.1@1420.11,428.35 1420.11,350.11 ; 1420,350 1440,330 1595,330 v1(1630,365) 1630,428.04 ; U13.4@1474.25,998.81 1474.25,1055.75 1477,1058.5 v1(1477,1064) ; U5.8@1561.75,615 1628,615 v1(1630,617) ; D15.1@1603.21,425 D15.1@1600.18,428.04 1630,428.04 ; v1(1630,1790) 1645.87,1805.87 U15.1@1666.6,1805.87 ; D11.1@1660.19,428.35 1659.88,428.04 1630,428.04 ; v1(1726.39,1135.76) U4.8@1780.25,1135.76
  Top Layer w10: U4.8@1779.02,1137 U4.8@1780.25,1135.76
  Bottom Layer w8: v1(936,614) 966,614 970.97,618.97 C2.2@970.97,657.23 ; C4.2@1200,1141.5 1226.5,1141.5 v1(1240,1155) ; v1(1300,615) 1315,615 1320,620 C13.2@1320,657.23 ; v1(1477,1064) 1477,1053 1477.19,1052.81 C58.2@1477.19,1015.86 ; v1(1630,617) 1630,645 1640,655 1667.53,655 C23.2@1669.03,653.5 ; C26.2@1680.71,1160 C26.2@1672.97,1152.26 1689.47,1135.76 v1(1726.39,1135.76)
  other v1: 750,1066
15V: C52.1 C57.1 L2.2 U12.4 | length 324.5
  Top Layer w10: U12.4@641.12,321.29 680.71,321.29 v1(695,307)
  Bottom Layer w8: C52.1@598.66,420.57 C52.1@595.36,417.27 595.36,421.36 v1(631,457)
  Bottom Layer w10: v1(450.25,456.13) 432.91,456.13 423.07,446.29 423.07,384.65 C57.1@454.64,353.08 C57.1@452.56,351
  Bottom Layer w25: v1(710,830) L2.2@775,830
A+: C6.2 C8.1 J14.5 R4.1 R7.1 | length 960.1
  Top Layer w8: R7.1@1108.11,547 1108.11,573.11 1109,574 v1(1109,582)
  Bottom Layer w8: v1@1109,576 v1(1109,582) 1192.43,582 1224.43,550 1224.43,504.88 1224.62,504.88 C8.1@1255,474.5 1255,434.06 R4.1@1280.52,408.54 ; R4.1@1289.52,408.54 1281,400.02 1281,336 1248.9,303.9 1248.9,113.65 1278.42,84.13 1464.13,84.13 J14.5@1525,145
A-: C3.2 C6.1 J14.6 R2.1 R4.2 | length 1049.8
  Top Layer w8: R2.1@1173.88,547.01 1173.88,528.12 1193,509 v1(1196,512)
  Bottom Layer w8: C3.2@1157,474.5 1194.97,474.5 1196,475.54 ; v1(1196,512) 1196,475.54 ; C6.1@1217.53,337 R4.2@1217.53,408.54 1196,430.07 1196,475.54 ; C6.1@1225.1,335.57 1225.1,115 1271.85,68.25 1547.61,68.25 1575,95.65 1575,195 J14.6@1525,245 J14.6@1530,245
AbsEnc1-5V: C63.1 J7.7 R48.2 U9.6 | length 659
  Top Layer w8: v1(410,1890) 434.13,1914.13 U9.6@458.6,1914.13
  Top Layer w25: J7.7@140,1790 140,1730 170,1700 270,1700 320,1750 320,1858.78 351.22,1890 v1(410,1890)
  Bottom Layer w8: J7.7@140,1790 140,1676.38 R48.2@141.38,1675
AbsEnc2-5V: C65.1 J8.7 R54.2 U15.6 | length 1318.5
  Top Layer w8: v1(1630,1900) 1644.13,1914.13 U15.6@1666.6,1914.13 ; v1(2060,1715) 2035,1715 2005,1745 2005,2035 J8.7@2060,2090 J8.7@2071,2079
  Bottom Layer w8: R54.2@2003.62,1676.84 2005,1678.22 2005,1705 2015,1715 v1(2060,1715)
  Bottom Layer w25: 1610,1960 1602,1968 1602,2148.5 1678.5,2225 1925,2225 J8.7@2060,2090
B+: C16.2 C18.1 J14.3 R13.1 R16.1 | length 742.6
  Top Layer w8: v1(1292.17,507.47) 1292.17,527.29 R16.1@1311.89,547.01
  Bottom Layer w8: v1@1292.53,507.47 v1(1292.17,507.47) 1291,506.3 1291,486 1302.5,474.5 C18.1@1347,474.5 1347,425.05 R13.1@1363.5,408.54 C16.2@1363.5,337 1331.73,305.23 1300.05,305.23 1264.77,269.95 1264.77,120.23 1285,100 1385,100 1425,140 J14.3@1425,145 ; C18.1@1354.24,474.24 C18.1@1355,473.48
B-: C14.2 C16.1 J14.4 R11.1 R13.2 | length 640.4
  Top Layer w8: R11.1@1472.14,547.01 1472.14,527.86 v1(1492,508)
  Bottom Layer w8: J14.4@1425,245 1420,245 1375,200 1365,200 1364.35,200.65 1306.63,200.65 1280.65,226.63 1280.65,263.37 1306.63,289.35 1378.85,289.35 C16.1@1426.5,337 R13.2@1426.5,408.54 1426.5,456 C14.2@1445,474.5 1478.5,508 v1(1492,508)
C1+: C40.1 J7.2 R47.2 | length 1083
  Bottom Layer w8: J7.2@240,2090 341.22,1988.78 341.22,1688.78 387,1643 590,1643 667,1720 749.75,1720 ; C40.1@752.5,1760 752.5,1722.75 749.75,1720 ; R47.2@872.5,1680 832.5,1720 749.75,1720
C1-: C39.2 J7.4 R42.2 | length 1128
  Bottom Layer w8: J7.4@240,1990 265,1990 320,1935 320,1680 539,1461 852,1461 872.5,1481.5 C39.2@872.5,1520 R42.2@872.5,1600
C2+: C46.1 J8.2 R63.2 | length 929.2
  Bottom Layer w8: R63.2@1308.5,1610 C46.1@1308.5,1530 1310,1528.5 1310,1495 1360,1445 1615,1445 J8.2@1960,1790
C2-: C45.2 J8.4 R58.2 | length 788.6
  Top Layer w8: v1(1420,1728) 1798,1728 J8.4@1960,1890
  Bottom Layer w8: R58.2@1308.5,1690 1308.5,1728 ; C45.2@1308.5,1760 1308.5,1728 ; v1(1420,1728) 1308.5,1728
D1+: C37.1 J7.6 R38.1 R39.2 | length 553.5
  Top Layer w8: J7.6@240,1890 443.5,2093.5 C37.1@444,2093.5 R38.1@567,2093.5 640,2020.5 640,1981.5
D1-: C36.2 J7.8 R34.2 R38.2 | length 974.2
  Top Layer w8: v1(498,2140) 514.5,2156.5 R38.2@567,2156.5 R34.2@690,2156.5 C36.2@813,2156.5
  Bottom Layer w8: J7.8@240,1790 196,1834 196,1871.27 195.65,1871.63 195.65,2108.73 226.92,2140 v1(498,2140)
D2+: C43.1 J8.6 R53.1 R55.2 | length 544.1
  Top Layer w8: R55.2@1560,1961.5 1560,2039.5 R53.1@1614,2093.5 1615,2094.5 C43.1@1737,2094.5 1855.5,2094.5 J8.6@1960,1990
D2-: C42.2 J8.8 R49.2 R53.2 | length 619.5
  Top Layer w8: C42.2@1368,2156.5 R49.2@1491,2156.5 R53.2@1614,2156.5 1643.5,2156.5 1670,2130 v1(1690,2130)
  Bottom Layer w8: v1(1690,2130) 1890,2130 1930,2090 J8.8@1960,2090
Enc1-CLK: J2.2 J11.1 R46.1 U8.4 | length 3284.3
  Top Layer w8: U8.4@948.28,1695 955,1701.72 v1(955,1755) ; J2.2@1900,1214.98 1942.39,1172.6 1942.39,495.39 1913,466 1875,466 1855.87,446.87 1855.87,284.13 1880,260 1910,260 1942.39,227.61 1942.39,127.61 J11.1@1990,80
  Bottom Layer w8: R46.1@954.5,1682.5 955,1683 v1(955,1755) 1035,1755 1072.38,1717.62 1072.38,1415.9 1110.27,1378 1640.35,1378 1827.35,1565 1990,1565 2029.13,1525.87 2029.13,1344.11 J2.2@1900,1214.98
Enc1-TxEn: J2.8 J13.2 R37.2 R40.1 U7.3 | length 3535.1
  Top Layer w8: U7.3@948.36,1916.5 948.36,1896.82 955,1890.18 v1@989.82,1890.18 ; v1(995,1895) 995,1872.5 R37.2@1025,1842.5
  Power Layer w8: J13.2@1395,1305 1465,1235 1770,1235 1845,1160 1845,969.98 J2.8@1900,914.98 1909.98,914.98 1955,960 1955,1040 1980,1065 2051,1065 2090,1026 v1(2090,965)
  Bottom Layer w8: v1@995,1892.63 1081.63,1806 1081.63,1805.9 1095.9,1791.63 1096,1791.63 1120,1767.63 1120,1435.63 1130,1425.63 1620.63,1425.63 1807.62,1612.62 2009.73,1612.62 2092,1530.35 2090,1528.35 v1(2090,965) ; v1(995,1895) 980,1910 980,1940 988.5,1948.5 R40.1@1014.87,1948.5
Enc2-CLK: J2.6 J10.1 R62.1 U11.4 | length 2910.4
  Top Layer w8: U11.4@1249,1545 1265,1529 v1(1265,1500) 1274.13,1490.87 1448.42,1490.87 1550.3,1592.75 1930.05,1592.75 2130,1392.8 2130,981.92 2130.25,981.67 2130.25,948.33 2130,948.08 2130,400 J10.1@2110,380
  Power Layer w8: v1(1970,865) 1957.61,852.61 1957.61,585.04 1985.29,557.37 2032.63,557.37 v1(2050,540)
  Bottom Layer w8: R62.1@1224.5,1460.78 v1@1263.71,1500 ; J2.6@1900,1014.98 1950,964.98 1950,890 1970,870 v1(1970,865) ; v1(2050,540) 2050,440 J10.1@2110,380 J10.1@2090,360
Enc2-TxEn: J2.19 J10.2 R52.2 R56.1 U10.3 | length 2930.2
  Top Layer w8: R52.2@1140,1858.5 1100,1818.5 1100,1585 1210,1475 1455,1475 1556.87,1576.87 1923.47,1576.87 2114.13,1386.22 2114.13,975.34 2114.37,975.1 2114.37,954.9 2114.13,954.66 2114.13,653.13 2114,653 2114,514 2064,464 1975,464 1951,440 1951,363.98 J2.19@2000,314.98 2075.02,314.98 J10.2@2110,280 ; R52.2@1146.5,1865 U10.3@1232.72,1865
  Bottom Layer w8: v1@1116.5,1821.5 R56.1@1153.63,1821.5
  other v1: 1106,1816
eQEP1-I: J13.1 R31.2 U6.1 | length 416.6
  Top Layer w8: J13.1@1495,1305 1567.35,1305 1671.72,1409.37 1770.63,1409.37 v1@1772.59,1407.41 ; v1(1774,1406) v1@1772.59,1407.41 ; U6.1@1813.46,1405 U6.1@1815.87,1407.41 v1@1772.59,1407.41
  Bottom Layer w8: R31.2@1735,1423.62 1751.38,1423.62 1769,1406 v1(1774,1406)
eQEP1B: J1.14 J2.4 J12.1 | length 4281.2
  Top Layer w8: J1.14@200,620 140,560 140,160 200,100 730.1,100 777.72,52.38 1741.85,52.38 1840,150.53 1840,1054.98 J2.4@1900,1114.98
  Power Layer w8: J2.4@1900,1114.98 J2.4@1900,1125
  Bottom Layer w8: J2.4@1900,1114.98 1855,1069.98 1855,880 1875,860 1930,860 1950,840 1950,250 J12.1@1990,210
ExIn: J1.19 R69.1 | length 224.3
  Top Layer w8: J1.19@300,320 333,320 359.13,346.13 359.13,426.95 R69.1@411.15,478.97
ExOut: C50.1 J15.2 | length 335.3
  Bottom Layer w10: C50.1@849,427 958,427 1065,320 J15.2@1065,245
External-5V: J5.1 J6.1 | length 239.7
  Top Layer w50: J5.1@350,1440 445.79,1344.21 J6.1@550,1344.21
